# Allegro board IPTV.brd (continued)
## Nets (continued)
DDRA_ADDR13: R207.1 U9.T3(A13/NC)
DDRA_ADDR13_R: IC13.AL35(DDRA_ADR13) R207.2
DDRA_ADDR14: R200.1 U9.T7(NC5)
DDRA_ADDR14_R: IC13.AF38(DDRA_ADR14) R200.2
DDRA_BA0: R221.1 U9.M2(BA0)
DDRA_BA0_R: IC13.Y37(DDRA_BA0) R221.2
DDRA_BA1: R219.1 U9.N8(BA1)
DDRA_BA1_R: IC13.AA36(DDRA_BA1) R219.2
DDRA_BA2: R220.1 U9.M3(BA2)
DDRA_BA2_R: IC13.AA35(DDRA_BA2) R220.2
DDRA_CASN: R204.1 U9.K3(CAS)
DDRA_CASN_R: IC13.AL36(DDRA_CASN) R204.2
DDRA_CKE0: IC13.Y38(DDRA_CKE0) R188.2 U9.K9(CKE)
DDRA_CKN0: R259.1 R628.2 R629.1 R631.1 U9.K7(CK)
DDRA_CKN0_R: IC13.AH35(DDRA_CKN0) R259.2
DDRA_CKP0: R260.1 R626.1 R627.2 R631.2 U9.J7(CK*)
DDRA_CKP0_R: IC13.AH36(DDRA_CKP0) R260.2
DDRA_CSN0: R203.1 U9.L2(CS)
DDRA_CSN0_R: IC13.AM38(DDRA_CSN0) R203.2
DDRA_DM0: IC13.T37(DDRA_DM0) U9.E7(LDM)
DDRA_DM1: IC13.N38(DDRA_DM1) U9.D3(UDM)
DDRA_DQ0: IC13.H37(DDRA_DQ0) U9.F8(DQ3)
DDRA_DQ1: IC13.H38(DDRA_DQ1) U9.F7(DQ1)
DDRA_DQ2: IC13.G38(DDRA_DQ2) U9.H7(DQ7)
DDRA_DQ3: IC13.G37(DDRA_DQ3) U9.H8(DQ5)
DDRA_DQ4: IC13.T38(DDRA_DQ5) U9.E3(DQ0)
DDRA_DQ5: IC13.U38(DDRA_DQ4) U9.G2(DQ6)
DDRA_DQ6: IC13.U37(DDRA_DQ6) U9.H3(DQ4)
DDRA_DQ7: IC13.U36(DDRA_DQ7) U9.F2(DQ2)
DDRA_DQ8: IC13.L36(DDRA_DQ11) U9.D7(DQ8)
DDRA_DQ9: IC13.L37(DDRA_DQ9) U9.B8(DQ14)
DDRA_DQ10: IC13.L38(DDRA_DQ10) U9.A7(DQ12)
DDRA_DQ11: IC13.K38(DDRA_DQ8) U9.C8(DQ10)
DDRA_DQ12: IC13.P37(DDRA_DQ13) U9.A3(DQ15)
DDRA_DQ13: IC13.P38(DDRA_DQ12) U9.A2(DQ13)
DDRA_DQ14: IC13.R35(DDRA_DQ14) U9.C2(DQ11)
DDRA_DQ15: IC13.R36(DDRA_DQ15) U9.C3(DQ9)
DDRA_DQSN0: IC13.J36(DDRA_DQSN0) U9.G3(LDQS*)
DDRA_DQSN1: IC13.N35(DDRA_DQSN1) U9.B7(UDQS*)
DDRA_DQSP0: IC13.J35(DDRA_DQSP0) U9.F3(LDQS)
DDRA_DQSP1: IC13.N36(DDRA_DQSP1) U9.C7(UDQS)
DDRA_ODT0: R201.1 U9.K1(ODT)
DDRA_ODT0_R: IC13.AM36(DDRA_ODT0) R201.2
DDRA_RASN: R202.1 U9.J3(RAS)
DDRA_RASN_R: IC13.AM37(DDRA_RASN) R202.2
DDRA_REF\G: C288.2 C293.2 C294.1 IC13.N28(DDRA_REF1) IC13.R28(DDRA_REF2) IC13.Y28(DDRA_REF3) R191.2 R192.1
DDRA_RESETN\G: R189.2 R617.1 R619.1 R620.2 R638.1
DDRA_VREF_CA: C465.1 C466.1 C467.1 C468.2 R624.2 R625.1 U9.M8(VREFCA)
DDRA_VREF_DQ: C461.1 C462.1 C463.1 C464.2 R622.1 R623.2 U9.H1(VREFDQ)
DDRA_WEN: R231.1 U9.L3(WE)
DDRA_WEN_R: IC13.Y36(DDRA_WEN) R231.2
DDRB_ADDR0: R281.1 U10.N3(A0)
DDRB_ADDR0_R: IC13.C37(DDRB_ADR0) R281.2
DDRB_ADDR1: R261.1 U10.P7(A1)
DDRB_ADDR1_R: IC13.D29(DDRB_ADR1) R261.2
DDRB_ADDR2: R289.1 U10.P3(A2)
DDRB_ADDR2_R: IC13.B38(DDRB_ADR2) R289.2
DDRB_ADDR3: R287.1 U10.N2(A3)
DDRB_ADDR3_R: IC13.B32(DDRB_ADR3) R287.2
DDRB_ADDR4: R268.1 U10.P8(A4)
DDRB_ADDR4_R: IC13.C35(DDRB_ADR4) R268.2
DDRB_ADDR5: R272.1 U10.P2(A5)
DDRB_ADDR5_R: IC13.D33(DDRB_ADR5) R272.2
DDRB_ADDR6: R266.1 U10.R8(A6)
DDRB_ADDR6_R: IC13.B36(DDRB_ADR6) R266.2
DDRB_ADDR7: R284.1 U10.R2(A7)
DDRB_ADDR7_R: IC13.A32(DDRB_ADR7) R284.2
DDRB_ADDR8: R264.1 U10.T8(A8)
DDRB_ADDR8_R: IC13.C36(DDRB_ADR8) R264.2
DDRB_ADDR9: R280.1 U10.R3(A9)
DDRB_ADDR9_R: IC13.D32(DDRB_ADR9) R280.2
DDRB_ADDR10: R265.1 U10.L7(A10/AP)
DDRB_ADDR10_R: IC13.C29(DDRB_ADR10) R265.2
DDRB_ADDR11: R263.1 U10.R7(A11)
DDRB_ADDR11_R: IC13.A37(DDRB_ADR11) R263.2
DDRB_ADDR12: R277.1 U10.N7(A12/BC-)
DDRB_ADDR12_R: IC13.C32(DDRB_ADR12) R277.2
DDRB_ADDR13: R262.1 U10.T3(A13/NC)
DDRB_ADDR13_R: IC13.B37(DDRB_ADR13) R262.2
DDRB_ADDR14: R288.1 U10.T7(NC5)
DDRB_ADDR14_R: IC13.C33(DDRB_ADR14) R288.2
DDRB_BA0: R275.1 U10.M2(BA0)
DDRB_BA0_R: IC13.A28(DDRB_BA0) R275.2
DDRB_BA1: R267.1 U10.N8(BA1)
DDRB_BA1_R: IC13.A29(DDRB_BA1) R267.2
DDRB_BA2: R270.1 U10.M3(BA2)
DDRB_BA2_R: IC13.B29(DDRB_BA2) R270.2
DDRB_CASN: R278.1 U10.K3(CAS)
DDRB_CASN_R: IC13.D36(DDRB_CASN) R278.2
DDRB_CKE0: IC13.D27(DDRB_CKE0) R197.1 U10.K9(CKE)
DDRB_CKN0: R282.1 R643.2 R644.1 R645.1 U10.K7(CK)
DDRB_CKN0_R: IC13.B34(DDRB_CKN0) R282.2
DDRB_CKP0: R286.1 R641.1 R642.2 R645.2 U10.J7(CK*)
DDRB_CKP0_R: IC13.A34(DDRB_CKP0) R286.2
DDRB_CSN0: R269.1 U10.L2(CS)
DDRB_CSN0_R: IC13.D37(DDRB_CSN0) R269.2
DDRB_DM0: IC13.C25(DDRB_DM2) U10.E7(LDM)
DDRB_DM1: IC13.A22(DDRB_DM3) U10.D3(UDM)
DDRB_DQ0: IC13.B16(DDRB_DQ18) U10.H8(DQ5)
DDRB_DQ1: IC13.B17(DDRB_DQ17) U10.F8(DQ3)
DDRB_DQ2: IC13.A17(DDRB_DQ16) U10.F7(DQ1)
DDRB_DQ3: IC13.A16(DDRB_DQ19) U10.H7(DQ7)
DDRB_DQ4: IC13.B25(DDRB_DQ20) U10.F2(DQ2)
DDRB_DQ5: IC13.A25(DDRB_DQ21) U10.E3(DQ0)
DDRB_DQ6: IC13.A26(DDRB_DQ22) U10.G2(DQ6)
DDRB_DQ7: IC13.B26(DDRB_DQ23) U10.H3(DQ4)
DDRB_DQ8: IC13.A19(DDRB_DQ24) U10.B8(DQ14)
DDRB_DQ9: IC13.B19(DDRB_DQ25) U10.C8(DQ10)
DDRB_DQ10: IC13.B20(DDRB_DQ27) U10.A7(DQ12)
DDRB_DQ11: IC13.A20(DDRB_DQ26) U10.D7(DQ8)
DDRB_DQ12: IC13.B23(DDRB_DQ28) U10.A3(DQ15)
DDRB_DQ13: IC13.C23(DDRB_DQ30) U10.A2(DQ13)
DDRB_DQ14: IC13.A23(DDRB_DQ29) U10.C3(DQ9)
DDRB_DQ15: IC13.C24(DDRB_DQ31) U10.C2(DQ11)
DDRB_DQSN0: IC13.D18(DDRB_DQSN2) U10.G3(LDQS*)
DDRB_DQSN1: IC13.C21(DDRB_DQSN3) U10.B7(UDQS*)
DDRB_DQSP0: IC13.C18(DDRB_DQSP2) U10.F3(LDQS)
DDRB_DQSP1: IC13.D21(DDRB_DQSP3) U10.C7(UDQS)
DDRB_ODT0: R285.1 U10.K1(ODT)
DDRB_ODT0_R: IC13.D35(DDRB_ODT0) R285.2
DDRB_RASN: R274.1 U10.J3(RAS)
DDRB_RASN_R: IC13.D38(DDRB_RASN) R274.2
DDRB_REF\G: C309.2 C314.2 C315.1 IC13.L21(DDRB_REF1) IC13.L23(DDRB_REF2) IC13.L26(DDRB_REF13) R198.2 R199.1
DDRB_RESETN\G: R193.2 R636.1 R637.2
DDRB_VREF_CA: C469.1 C470.1 C471.1 C472.2 R639.2 R640.1 U10.M8(VREFCA)
DDRB_VREF_DQ: C474.1 C475.1 C478.1 C481.2 R634.2 R646.1 U10.H1(VREFDQ)
DDRB_WEN: R279.1 U10.L3(WE)
DDRB_WEN_R: IC13.B28(DDRB_WEN) R279.2
DIFF_HDMI_0N\G: IC13.AU22(HDMI_TX0M) U15.2 U15.9 XP1.9
DIFF_HDMI_0P\G: IC13.AV22(HDMI_TX0P) U15.1 U15.10 XP1.7
DIFF_HDMI_1N\G: IC13.AU23(HDMI_TX1M) U15.5 U15.6 XP1.6
DIFF_HDMI_1P\G: IC13.AV23(HDMI_TX1P) U15.4 U15.7 XP1.4
DIFF_HDMI_2N\G: IC13.AT24(HDMI_TX2M) U16.2 U16.9 XP1.3
DIFF_HDMI_2P\G: IC13.AR24(HDMI_TX2P) U16.1 U16.10 XP1.1
DIFF_HDMI_CLKN\G: IC13.AR21(HDMI_TXCN) U16.5 U16.6 XP1.12
DIFF_HDMI_CLKP\G: IC13.AT21(HDMI_TXCP) U16.4 U16.7 XP1.10
DIFF_USB0D_N\G: IC13.AU28(USB0_DM) R630.2
DIFF_USB0D_P\G: IC13.AV28(USB0_DP) R621.2
EBI_DQ0\G: IC2.29(I/O0) IC13.Y1(EBI_DQ0/GPIO4_0)
EBI_DQ1\G: IC2.30(I/O1) IC13.Y2(EBI_DQ1/GPIO4_1)
EBI_DQ2\G: IC2.31(I/O2) IC13.W1(EBI_DQ2/GPIO4_2)
EBI_DQ3\G: IC2.32(I/O3) IC13.W2(EBI_DQ3/GPIO4_3)
EBI_DQ4\G: IC2.41(I/O4) IC13.W3(EBI_DQ4/GPIO4_4)
EBI_DQ5\G: IC2.42(I/O5) IC13.W4(EBI_DQ5/GPIO4_5)
EBI_DQ6\G: IC2.43(I/O6) IC13.V3(EBI_DQ6/GPIO4_6)
EBI_DQ7\G: IC2.44(I/O7) IC13.V4(EBI_DQ7/GPIO4_7)
ENET_ACTIVITY_LEDB\G: IC13.AR1(TSI0_D2/VIU0_DAT2) R271.1
ENET_IND\G: IC13.AR2(TSI0_D3/VIU0_DAT3) R355.2
ETH_RSTN\G: R315.2 R364.2 R366.1
FE0_DUPLEX: IC8.16(RXD0/RXD0/DUPLE) R132.2 R311.2
FUNSEL\G: IC13.C13(FUNSEL) R230.1
HDMI_CEC\G: IC13.AV20(SIO2_DIN/GPIO2_6/HDMI_CEC) U14.1 XP1.13
HDMI_HOT_PLUG\G: C247.1 D20.3 IC13.AT19(SIO2_BCLK/GPIO2_3) R146.1 U14.6 XP1.19
I2C3_SCL\G: C178.1 IC13.AB2(NF_CSN1/I2C3_SCL) R38.1 R59.2
I2C3_SDA\G: C72.1 IC13.AC1(NF_RDY1/I2C3_SDA) R37.1 R62.2
IR_IN\G: D37.1(OUT) IC13.C11(GPIO5_4/IR_IN) R119.2
IR_LED_INDIC\G: IC13.AP2(TSI0_D1/VIU0_DAT1) LED12.2(C)
JTAG_SEL\G: IC13.AU7(JTAG_SEL/GPIO2_7) R45.1 R46.1 R81.1
LED0_LINK_ACT\G: R114.1 R130.2
LED_WLAN: LED8.2(C) R349.2
LNA_CORE_VDD1P2: C320.1 C322.1 FB1.1 U18.23(LNA_CORE1_VDD1P2) U18.27(LNA_CORE0_VDD1P2)
LOGEN_VDD1P2: C355.2 R333.1 U18.26(LOGEN_VDD1P2)
MDCK\G: IC8.12(MDC) R242.2
MDIO\G: IC8.11(MDIO) IC13.AU38(GPIO11_0/MDIO) R233.1
MUTE_CTL\G: IC13.C5(EBI_ADR3/GPIO7_1) R88.1(A)
NF_ADNUM\G: IC13.AT37(NF_ADNUM/GPIO0_0) R227.1 R236.1
NF_ALE\G: IC2.17(AL) R57.1
NF_BLKSIZE\G: IC13.AV37(NF_BLKSIZE/GPIO10_7) R224.1 R242.1
NF_BOOTBW\G: IC13.AA3(NF_WEN/NF_BOOTBW) R41.1 R42.1 R63.2
NF_CLE\G: IC2.16(CL) R58.1
NF_CSN0\G: IC2.9(E*) IC13.AB3(NF_CSN0/SDIO_CCMD) R98.1
NF_CSN1\G: R59.1 R143.2
NF_PAGE0\G: IC13.AR36(NF_PAGE0/GPIO0_1) R228.1 R235.1
NF_PAGE1\G: IC13.AR37(NF_PAGE1/GPIO0_2) R225.1 R234.1
NF_RDY0\G: IC2.7(RB*) IC13.AC2(NF_RDY0/SDIO_CARD_DETECT) R97.1
NF_RDY1\G: R62.1 R142.2
NF_REN\G: IC2.8(R*) IC13.AB1(NF_REN/SDIO_CARD_POWER_EN)
NF_WEN\G: IC2.18(W*) R63.1
NF_WP\G: IC2.19(WP*) R139.2
NFC_ECC0\G: IC13.B2(EBI_ADR15/GPIO11_6) R293.1 R297.1
NFC_ECC1\G: IC13.A2(EBI_ADR12/GPIO11_2) R223.1 R295.1
NFC_ECC2\G: IC13.D1(EBI_ADR11/GPIO11_1) R222.1 R229.1
PCIE_CLKOUTN: C194.2 R66.2 R73.1
PCIE_CLKOUTP: C193.2 R65.2 R72.1
PCIE_CLKREQ: R94.1 R319.2 R323.2 R354.2
PCIE_RDN: IC13.M4(PCIE_RX0M) R339.2
PCIE_RDP: IC13.M3(PCIE_RX0P) R337.2
PCIE_RST: R96.1 R106.2 R328.2 R341.2
PCIE_TDN: C358.1 R347.2
PCIE_TDP: C359.1 R343.2
PCIE_WAKE_L: R91.1 R93.2 R324.2 R325.2
PHY0_AD1: IC8.14(RXD2/PHYAD1) R312.2 R313.2
POWER_LED_INDIC\G: IC13.AP1(TSI0_D0/VIU0_DAT0) R457.1
RESET_DDR3\G: R620.1 R637.1 R647.2 R648.2
RESET_SYS\G: C338.1(A) IC13.C6(RESET_SYS) R20.2(B) R316.2 R647.1
RF_DISABLE_N: R99.1 R102.2 R327.2 R332.2
ROMBOOT_SEL\G: IC13.D9(ROMBOOT_SEL/SPI_SCLK) R47.1 R48.1
RX+_PHY0\G: R127.2 R309.1 TR2.6(RD+) U17.3
RX-_PHY0\G: R126.2 R303.1 TR2.8(RD_) U17.4
RXD0_RMII0: IC13.AP37(GPIO1_7/MII0_RXD0) R132.1
RXD1_RMII0: IC13.AP38(GPIO1_6/MII0_RXD1) R154.1
RXDV_RMII0: IC13.AR38(GPIO1_5/MII0_RXDV) R302.1
RXG_0: C238.1 U21.3(J2)
RXG_1: C334.1 U19.1(J3)
SD_CCLK_OUT: IC13.AU34(MII2_TXCK/PWM_OUT0) U12.5(P5)
SD_CCMD: R149.1 R239.2 U12.2(P2)
SD_CDATA0: R150.1 R160.2 U12.7(P7)
SD_CDATA1: R151.1 R296.2 U12.8(P8)
SD_CDATA2: R147.1 R238.2 U12.9(P9)
SD_CDATA3: R148.1 R237.2 U12.1(P1)
SD_CWPR: R152.1 R241.2 U12.11(P11)
SD_DETECT: R153.1 R292.2 U12.10(P10)
SD_POWER_EN: R164.2 R166.2 R294.2
SELF_BOOT\G: IC13.C9(SELF_BOOT/SPI_SDO) R43.1 R44.1
SFC_CLK\G: R64.2 TP1.1 U11.6(A1)
SFC_CSN1: IC13.AJ2(SFC_CS1N/GPIO12_6) R167.1 U11.1(SDA)
SFC_DIO: IC13.AK3(SFC_DIO/GPIO12_0) R157.2
SFC_DOI: IC13.AH2(SFC_DOI/GPIO12_3) R112.1
SFC_HOLDN: IC13.AJ1(SFC_HOLD_IO3/GPIO12_4) R170.1 U11.7(A0)
SFC_WPN: IC13.AJ3(SFC_WP_IO2/GPIO12_1) R168.1 R169.2 U11.3(ALERT)
SPDIF_OUT\G: R81.2 XS7.3
STBY_PWROFF\G: IC13.C12(GPIO5_2/GPIO9_4) R61.1 R68.2 R69.2 R82.1 R89.1 R251.1
SYNTH_VCO_VDD1P2: C325.2 FB3.2 U18.36(SYNTH_VCO_VDD1P2)
SYNTH_VDD1P2: C329.2 FB2.2 U18.37(SYNTH_VDD1P2)
TCK_ICE\G: IC13.B14(JTAG_TCK) R249.1
TDI: R344.2 R349.1 U18.3(GPIO3/LED_WLAN/TDI)
TDI_ICE\G: IC13.A13(JTAG_TDI) R245.1
TDO_ICE\G: IC13.C14(JTAG_TDO) R244.1
TMS_ICE\G: IC13.A14(JTAG_TMS) R248.1
TRST_ICE\G: IC13.B13(JTAG_TRSTN) R250.1
TX+_PHY0\G: R129.2 R310.2 TR2.1(TD+) U17.1
TX-_PHY0\G: R128.2 R308.2 TR2.3(TD_) U17.6
TX_2G_CORE_VDD1P2: C241.1 C249.2 C374.1 R318.2 U18.21(TX_2G_CORE1_VDD1P2) U18.29(TX_2G_CORE0_VDD1P2)
TXD0_RMII0\G: IC8.24(TXD0/TXD0) R235.2
TXD1_RMII0\G: IC8.25(TXD1/TXD1) R236.2
TXEN_RMII0: IC8.23(TXEN/TX_EN) R234.2
TXG_0: C228.1 L31.2 R334.2
TXG_0_SW_IN: C332.1 R336.2 U21.1(J3)
TXG_1: C327.1 L26.2 R252.2
TXG_1_SW_IN: C373.1 R345.2 U19.3(J2)
UART0_RXD\G: IC13.AU25(GPIO3_0/UART0_RXD) R485.1
UART0_TXD\G: IC13.AV25(GPIO3_1/UART0_TXD) R479.1
USB0_PWREN\G: IC13.AU26(USB0_PWREN/GPIO7_7) R103.2 R253.1 R301.1
USB1_PWREN\G: IC13.AT25(I2C1_SDA/USB1_PWREN) R107.2 R322.1 R329.1
USB1D_DM\G: IC13.AV29(USB1_DM) R604.2 U1.21(DMU)
USB1D_DP\G: IC13.AU29(USB1_DP) R603.2 U1.22(DPU)
USB_HUB_RST\G: C418.1 R363.2 R589.2 U1.37(SYSRSTB)
USB_HUB_XI: C422.1 R591.1 U1.10(X1) U2.1
USB_HUB_XO: C423.1 R590.2 R591.2 U2.3
USBHUB1_DM: R592.2 U3.3 XS5.2(D-)
USBHUB1_DP: R593.2 U3.4 XS5.3(D+)
USBHUB1_FLG: R606.2 U1.46(CSB1) U5.2(FLG)
USBHUB1_PWREN: R605.2 U1.45(PPB1) U5.1(EN)
USBHUB1_VBUS: C424.1 C425.1 R632.1 U5.6(OUT1) U5.8(OUT2) XS5.1(V)
USBHUB2_DM: R594.2 R604.1 U4.6 XS1.2(D-)
USBHUB2_DP: R595.2 R603.1 U4.1 XS1.3(D+)
USBHUB2_FLG: R609.2 U1.44(CSB2) U6.2(FLG)
USBHUB2_PWREN: R608.2 U1.43(PPB2) U6.1(EN)
USBHUB2_VBUS: C428.1 C431.1 L57.2 R633.1 U6.6(OUT1) U6.8(OUT2)
USBHUB3_DM: R596.2 R630.1 U4.3 XS10.2(D-)
USBHUB3_DP: R597.2 R621.1 U4.4 XS10.3(D+)
USBHUB3_FLG: R612.2 U1.41(CSB3) U7.2(FLG)
USBHUB3_PWREN: R611.2 U1.40(PPB3) U7.1(EN)
USBHUB3_VBUS: C432.1 C435.1 L51.2 R649.1 U7.6(OUT1) U7.8(OUT2)
USBHUB4_DM: R598.2 U3.1 XS4.2(D-)
USBHUB4_DP: R599.2 U3.6 XS4.3(D+)
USBHUB4_FLG: R615.2 U1.39(CSB4) U8.2(FLG)
USBHUB4_PWREN: R614.2 U1.38(PPB4) U8.1(EN)
USBHUB4_VBUS: C436.1 C439.1 R650.1 U8.6(OUT1) U8.8(OUT2) XS4.1(V)
VREG3P3: C365.1 R321.2 U18.35(VREG3P3_VDD3P3)
XIN\G: C272.1 IC13.A7(XIN) R186.1 XL1.1
XOUT\G: IC13.B7(XOUT) R186.2 R187.2
XTAL_IN: C242.1 U18.39(XTAL_IN) Y4.3
XTAL_OUT: R351.1 U18.38(XTAL_OUT)
XTAL_VDD2P5: C367.1 U18.40(XTAL_VDD2P5)
N305458: C25.2 C41.2 IC13.L17(DVDD33_STANDBY) L7.1
N331283: C20.2 C40.2 IC13.K17(VDD_STANDBY) L1.1
N371060: IC13.AN34(VPP_OTP) R36.1
N550713: C7.1 C19.1 C21.1 C157.1 C173.1 IC13.K14(VDDHV25_PLL_5) IC13.K15(VDDHV25_PLL_1) IC13.K16(VDDHV25_PLL_2) L2.1
N600656: C24.1 C158.1 C159.1 C162.1 C175.1 IC13.P15(VDDLV10_PLL5) IC13.P16(VDDLV10_PLL_1) IC13.P17(VDDLV10_PLL_2) L3.1
N617373: IC13.L1(PCIE_REFCLKP) R65.1
N617477: IC13.L2(PCIE_REFCLKM) R66.1
N620918: IC13.N10(PCIE_REXT) R71.1
N621324: C63.1 C67.2 C196.2 IC13.P11(PCIE_VP10_1) IC13.R11(PCIE_VP10_2) IC13.T11(PCIE_VP10_3) L5.1
N624580: C48.1 C180.2 C186.2 IC13.P10(PCIE_VP25_1) IC13.R10(PCIE_VP25_2) L6.1
N629124: IC13.AG4(SATA_REFCLKP) R70.1
N629220: IC13.AG3(SATA_REFCLKM) R70.2
N630094: IC13.W10(SATA_REXT) R67.1
N631154: C199.1 C200.2 C201.2 IC13.AA11(SATA_VP10_1) IC13.Y11(SATA_VP10_2) L8.1
N635359: C197.1 C198.2 IC13.AA10(SATA_VP25_1) IC13.Y10(SATA_VP25_2) L16.1
N672491: IC13.C2(EBI_ADR8/GPIO2_7) R54.1 R56.2
N675190: IC13.D2(EBI_ADR9/GPIO3_0) R52.1 R53.2
N675584: IC13.D3(EBI_ADR10/GPIO3_1) R49.1 R50.2
N683964: IC13.AJ4(SFC_CLK/GPIO12_2) R64.1
N742106: IC13.D25(DDRB_RESETN) R193.1
N743329: IC13.C16(DDRB_RTT) R194.1
N743719: IC13.K29(DDRB_HI) R195.1
N744113: IC13.L28(DDRB_LO) R196.1
N849049: IC13.V36(DDRA_RESETN) R189.1
N854645: IC13.G36(DDRA_RTT) R190.1
N855285: IC13.AB29(DDRA_HI) R17.1
N858511: IC13.AB28(DDRA_LO) R283.1
N952727: C26.2 C56.2 IC13.AB10(AVDD25_QAM) L34.2
N952924: C28.2 C57.2 IC13.AC11(AVDD10_QAM) L35.2
N965277: IC13.AT27(USB_REXT) R226.2
N968462: C30.1 C58.1 C59.1 IC13.AR27(AVDD33_USB1) IC13.AT28(AVDD33_USB2) L36.2
N1067717: C31.2 C61.2 IC13.AH25(DVDD10_USB) L37.1
N1077748: IC13.AP36(GPIO5_4/ETH0_REFCLK) R232.1
N1078134: C243.2 R232.2 R240.1
N1094266: IC13.AT36(ETH2_REFCLK/ETH1_REFCLK) R241.1
N1103649: IC13.AT33(USB0_OVRVUR/NFC_ECC_TYPE1) R237.1
N1103990: IC13.AU32(USB0_PWREN/NFC_ECC_TYPE0) R238.1
N1109849: IC13.AT34(USB1_PWREN/NFC_ECC_TYPE2) R239.1
N1115694: IC13.AT30(MII2_CRS/USB0_PWREN) R294.1
N1152398: JP1.3 R111.1 R485.2
N1152811: JP1.2 R101.1 R479.2
N1383679: IC13.AT12(VDAC0_IREF) R75.2 R77.2
N1387604: C202.2 C207.2 IC13.AT11(VDAC0_VDREF)
N1390073: C214.1 C217.1 C220.1 C221.1 IC13.AH14(AVDD3V3_VDAC0_1) IC13.AJ13(AVDD3V3_VDAC0_2) IC13.AJ14(AVDD3V3_VDAC0_3) IC13.AR10(AVDD3V3_VDAC0_4) L21.2
N1408395: IC13.AT13(VDAC1_IREF) R74.2 R76.2
N1409767: C205.2 C212.2 IC13.AR14(VDAC1_VDREF)
N1414099: C213.1 C215.1 C216.1 C219.1 IC13.AH15(AVDD3V3_VDAC1_1) IC13.AH16(AVDD3V3_VDAC1_2) IC13.AJ15(AVDD3V3_VDAC1_3) L22.2
N1446091: IC13.AU20(HDMI_REXT) R79.1 R80.1
N1450972: C227.1 C231.1 C233.1 C235.1 C236.1 C237.1 IC13.AH20(AVCC10_HDMI_1) IC13.AJ20(AVCC10_HDMI_2) IC13.AR22(AVCC10_HDMI_3) IC13.AT22(AVCC10_HDMI_4) L24.1
N1496909: C232.1 C234.1 IC13.AT8(ADAC_VCM)
N1501073: C223.1 C225.1 IC13.AT9(ADAC_VREFDAC)
N1511391: C226.1 C229.1 C230.1 IC13.AH10(AVDD33_ADAC_1) IC13.AJ10(AVDD33_ADAC_2) IC13.AR8(AVDD33_ADAC_3) L23.1
N1721272: C222.2 Q5.1(GATE) Q6.1(GATE) Q7.1(GATE) R9.2 R78.1 R84.1 R86.1
N1729801: R9.1 T7.3(C)
N1743891: R69.1 T7.1(B)
N1825143: C307.1(A) C308.2 D37.3(VS) R509.2
N1834854: LED10.1(COM) R414.2
N1835472: R355.1 R365.1 R368.1 R414.1
N1837681: LED10.2(R) R365.2 R410.1 T3.3(C)
N1839934: R410.2 T6.1(B)
N1841130: LED10.3(GY) T6.3(C)
N1846118: R273.2 R276.1 T3.1(B)
N1848580: R271.2 R273.1
N1851731: LED11.2(R) R472.2 R473.1 T4.3(C)
N1851759: R473.2 T5.1(B)
N1851767: LED11.3(GY) T5.3(C)
N1851843: R457.2 R458.1 T4.1(B)
N1851925: LED11.1(COM) R474.2
N2007180: C36.1 R28.2 R163.1
N2007522: IC9.6(OUT3) R28.1
N2007610: IC9.7(OUT2) TP31.1
N2007630: IC9.8(OUT1) TP30.1
N2053816: C92.1 C169.2 C171.2 IC5.1(VO) L12.1 L15.2 R87.2
N2054287: C92.2 IC5.2(VFB) R85.2 R87.1
N2062131: IC5.7(EN) R100.2
N2068150: C163.2 IC5.4(SS)
N2072854: C165.2 IC5.10(SW1) IC5.11(SW2) L15.1
N2075428: C165.1 IC5.12(VBST)
N2101818: C167.1 IC5.3(VREG5)
N2116419: C85.1 Q8.1(GATE) R254.2 R255.1 R301.2
N2117665: R254.1 T2.3(C)
N2151179: R103.1 T2.1(B)
N2292443: IC2.10(NC6) R143.1
N2293018: IC2.6(NC5) R142.1
N2300583: IC2.38(NC23) R144.1 R145.2
N2472672: C86.1 IC12.8(SS)
N2473836: C89.1 C174.1 IC12.6(COMP)
N2474741: C89.2 R104.1
N2480908: IC12.7(EN) R82.2 R123.1
N2490139: C93.2 IC12.1(BS)
N2491369: C93.1 IC12.3(SW) L10.1
N2496811: IC12.5(FB) R108.2 R109.1
N2616362: C47.1 C87.1 C107.2 C109.2 IC26.1(VO) L11.2 L14.1 R60.2
N2616386: C97.2 IC26.10(SW1) IC26.11(SW2) L11.1
N2616524: IC26.7(EN) R61.2 R134.1 R135.1
N2616548: C97.1 IC26.12(VBST)
N2616572: C108.1 IC26.3(VREG5)
N2616768: IC26.2(VFB) R15.2 R55.2 R60.1
N2616804: C94.2 IC26.4(SS)
N2642107: C115.1 IC14.8(SS)
N2642151: C116.1 C117.1 IC14.6(COMP)
N2642251: C116.2 R116.1
N2642341: C120.2 IC14.1(BS)
N2642373: C120.1 IC14.3(SW) L20.1
N2642473: IC14.7(EN) R124.1
N2642609: IC14.5(FB) R120.2 R121.1
N2653412: C348.1 IC17.8(SS)
N2653456: C118.1 C349.1 IC17.6(COMP)
N2653460: C346.1 C347.2 R51.1 R125.2
N2653540: C349.2 R583.1
N2653646: C350.2 IC17.1(BS)
N2653678: C350.1 IC17.3(SW) L46.1
N2653726: C37.1 C351.1 C352.1 C354.1 C380.1 L38.1 L46.2 R563.1
N2653778: IC17.7(EN) R89.2 R125.1
N2653914: IC17.5(FB) R563.2 R567.1
N2753223: XP2.1 XS2.1
N2764036: C110.1 C119.2 L18.1 R16.1 R18.1
N2782469: R16.2 R18.2 XP2.2
N2794854: LED1.2(C) R122.1
N2978313: L56.1 L57.1 XS1.1(V)
N2982528: L51.1 L55.1 XS10.1(V)
N2987765: C274.1 R187.1 XL1.2
N4126175: R584.1 R585.2 U1.47(VBUSM)
N4126191: C413.1 C414.1 L49.2 R587.1 U1.16(AVSS_R) U1.18(AVSS)
N4126235: R595.1 U1.29(DP2)
N4126359: R594.1 U1.28(DM2)
N4126443: R586.2 U1.13(BUS_B)
N4126465: R593.1 U1.26(DP1)
N4126501: R592.1 U1.25(DM1)
N4126581: C404.1 C405.1 L47.2 R585.1
N4126617: R590.1 U1.11(X2)
N4126645: R587.2 U1.15(RREF)
N4126967: C413.2 C414.2 L48.2 U1.17(AVDD1) U1.19(AVDD2)
N4126991: R588.2 U1.14(TEST)
N4127321: R598.1 U1.34(DM4)
N4127377: R599.1 U1.35(DP4)
N4127493: R597.1 U1.32(DP3)
N4127601: R596.1 U1.31(DM3)
N4207901: R600.1 U1.8(AMBER)
N4556901: R607.1 U5.5(ILIM)
N4601170: R610.1 U6.5(ILIM)
N4602996: R613.1 U7.5(ILIM)
N4604860: R616.1 U8.5(ILIM)
N4652480: C0603.1 R617.2 U9.T2(RST)
N4662264: R618.2 U9.L8(ZQ)
N4946648: R635.2 U10.L8(ZQ)
N4946958: C473.1 R638.2 U10.T2(RST)
N5731377: R157.1 U11.5(A2)
N5731391: R112.2 U11.2(SCL)
N5767868: IC13.AT32(USB1_PWREN/SDIO_CDATA0) R160.1
N5876384: IC13.AR30(MII2_COL/USB0_OVRCUR) R292.1
N5917875: IC13.AV32(USB1_OVRCUE/SDIO_CDATA1) R296.1
N6200242: C239.1 IC8.32(RST*) R298.1 R315.1 R316.1 R367.1
N6200318: C113.2 IC8.10(REXT) R113.1
N6200334: LED5.2(C) R114.2
N6200500: IC8.28(COL/CONFIG0) R118.1
N6200912: IC8.26(TXD2) R299.2
N6200944: IC8.27(TXD3) R300.2
N6201102: IC8.18(RXDV/CRSDV/CONFIG) R302.2
N6210871: R307.1 XS11.A7(P7) XS11.A8(P8)
N6210911: C152.2 R303.2 R309.2
N6210999: TR2.16(TX+) XS11.A1(TX+)
N6211019: TR2.14(TX_) XS11.A2(TX-)
N6211031: R306.1 XS11.A4(P4) XS11.A5(P5)
N6211051: TR2.11(RX+) XS11.A3(RX+)
N6211151: R305.1 TR2.15(CT3)
N6211171: R304.1 TR2.10(CT2)
N6211183: TR2.9(RX_) XS11.A6(RX-)
N6211413: C151.2 R308.1 R310.1
N6211447: C161.2 R304.2 R305.2 R306.2 R307.2
N6323561: IC8.15(RXD1/RXD1/PHYAD) R154.2
N6351542: IC8.13(RXD3/PHYAD) R314.2
N6375056: IC8.4(RX-) R126.1
N6376252: IC8.5(RX+) R127.1
N6391887: IC8.6(TX-) R128.1
N6393086: IC8.7(TX+) R129.1
N6403944: IC8.30(LED0/NWAYEN) R130.1
N6828557: IC8.31(LED1/SPEED) R131.1
N6828959: R131.2 TP33.1
N7088770: C27.1 C29.1 CAP3.1(A) L29.1 R19.2 TP10.1 U13.2(OUT) U13.4(H/S OUT)
N7088794: C46.2 R12.2 R19.1 U13.1(ADJ)
N16840469: IC13.R3(EBI_DQ13/GPIO6_5) R323.1
N16871257: IC13.T4(EBI_DQ12/GPIO6_4) R325.1
N16883109: IC13.B4(EBI_ADR14/GPIO11_5) R327.1
N16907829: IC13.T3(EBI_DQ11/GPIO6_3) R328.1
N16928233: C358.2 IC13.N1(PCIE_TX0P)
N16929752: C359.2 IC13.N2(PCIE_TXOP)
N17005896: R107.1 T8.1(B)
N17005931: C88.1 Q10.1(GATE) R322.2 R330.2 R331.1
N17006006: R330.1 T8.3(C)
N17042686: C250.1 U18.44(O_VREF_LDO)
N17042698: R353.2 U18.46(O_VDD1P3_RF)
N17042736: ANT1.1 C323.1 C372.1
N17042751: C373.2 L44.2 R252.1
N17042774: C240.1 C332.2 L39.2 L42.2 R334.1
N17042778: C240.2 L40.2
N17042826: R335.2 U18.1(GPIO5/BT_RST_N/EXT_POR_L)
N17042890: ANT2.1 C324.1 C376.1
N17042953: C224.1 R351.2 Y4.1
N17043028: R340.1 U18.34(RCAL_RES_EXT)
N17043046: C327.2 U18.18(PA_2G_CORE1)
N17043052: C334.2 U18.22(RF_2G_ANTENNA_CORE1)
N17043079: C356.2 R337.1
N17043089: C357.2 R339.1
N17043097: C357.1 U18.62(TDN0)
N17043198: R319.1 U18.55(PCIE_CLKREQ_L)
N17043200: L43.1 U23.4(SW)
N17043207: R338.1 R342.2 U18.47(JTAG_SEL)
N17043263: C335.2 R348.2 R350.2 U23.6(FB)
N17043371: C228.2 U18.32(PA_2G_CORE0)
N17043377: C238.2 U18.28(RF_2G_ANTENNA_CORE0)
N17043650: LED8.1(A) R29.1
N17043923: C194.1 U18.60(REFCLK_N)
N17044492: R343.1 U18.65(RDP0)
N17044502: R347.1 U18.66(RDN0)
N17044512: C356.1 U18.63(TDP0)
N17044516: C193.1 U18.59(REFCLK_P)
N17044572: R341.1 U18.58(PERST_L)
N17044582: R332.1 U18.57(RF_DISABLE_L)
N17044593: R324.1 U18.48(PCIE_PME_I)
N17408441: ANT3.1 C385.1 C387.1
N17408443: ANT6.1 C386.1 C387.2
N17411597: ANT4.1 C388.1 C390.1
N17411599: ANT5.1 C389.1 C390.2
N17473278: IC9.1(IN1) R115.2
N17474165: IC9.2(IN2) R117.2
N17571775: D5.2(K) L2.2 R178.2
N17602669: R20.1(A) R256.2(B) U20.2(VCC)
N17602677: C391.1(A) R356.2(B) R357.2(B) R397.2(B) U20.3(R\E\S\E\T\)
N17621483: C60.2(B) R136.1(A) U22.13(-INL)
N17621510: R7.2(B) R247.1(A) R258.2(B)
N17621572: C181.1 R137.2(B) R317.1(A) R359.1(A)
N17621582: C34.2(B) U22.8(CP)
N17621588: R7.1(A) U22.11(UVP)
N17621590: C35.2 U22.6(PVSS)
N17621599: C62.2(B) R257.2(B) R359.2(B) R360.1 U22.3(OUTR)
N17621615: C62.1(A) R317.2(B) U22.2(-INR)
N17621623: C268.2(B) R137.1(A)
N17621625: C34.1(A) U22.7(CN)
N17621631: C60.1(A) R133.1 R358.1(A) R361.1(A) U22.12(OUTL)
N17621647: C182.1 R90.1(A) R136.2(B) R358.2(B)
N17621657: C393.1(A) R90.2(B)
N17621659: C53.1(A) R88.2(B) R246.1(A) U22.5(EN)
N17668644: C255.2 Q9.1(GATE) R10.2 R165.1
N17668703: R10.1 T9.3(C)
N17668713: R164.1 T9.1(B)
N17692840: IC13.AU36(PWM_OUT1/I2C0_SDA) R363.1
N17694055: IC13.AU35(PWM_OUT2/I2C0_SCL) R364.1
N17732186: IC13.AU10(VDAC0_IOUT2) R171.2
N17732471: IC13.AV10(VDAC0_IOUT1) R172.2
N17732758: IC13.AV11(VDAC0_IOUT0) R173.2
N17739492: IC13.AV14(VDAC1_IOUT0) R177.1
N17739788: IC13.AU14(VDAC1_IOUT1) R176.1
N17782138: D6.1(A) L29.2
N17812204: LED12.1(A) R475.2
N17850380: R397.1(A) TP19.1

Pads without a net: IC2 1 2 3 4 5 11 14 15 20 21 22 23 24 25 26 27 28 33 34 35 39 40 45 46 47 48; IC5 6; IC8 8 19 20 21 22 29; IC13 A4 A5 A10 A11 AC37 AC38 AE1 AE3 AE4 AF1 AH1 AL1 AL2 AM1 AM2 AN3 AN4 AP3 AR3 AR4 AR5 AR6 AR15 AR16 AR18 AT2 AT3 AT4 AT5 AT6 AT15 AT16 AT18 AT26 AT35 AU1 AU2 AU3 AU4 AU5 AU16 AU17 AV2 AV4 AV5 AV16 AV17 AV26 AV34 AV35 B1 B3 B5 B10 B11 C3 C4 C8 C26 C27 C31 D4 D5 D8 D26 D31 E1 E2 E3 E4 G1 G2 G3 H1 H2 H3 J3 J4 K3 K4 R4 T1 T2 U1 U2 W36 W37 W38; IC26 6; JP1 5; MARK1 1; MARK2 1; MARK3 1; MARK4 1; MARK5 1; MARK6 1; TR2 4 5 12 13; U1 3 4 5 6 7; U5 4; U6 4; U7 4; U8 4; U9 J1 J9 L1 L9 M7; U10 J1 J9 L1 L9 M7; U18 2 4 5 8 9 10 11 24 25 33 41 50 52 54; U23 1; XP1 14

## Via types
v1: diameter 0.508, hole 0.305, TOP to BOTTOM, 1769 vias
v2: diameter 0.457, hole 0.254, TOP to BOTTOM, 615 vias
v3: diameter 1.27, hole 0.762, TOP to BOTTOM, 25 vias
v4: diameter 2.032, hole 1.524, TOP to BOTTOM, 3 vias

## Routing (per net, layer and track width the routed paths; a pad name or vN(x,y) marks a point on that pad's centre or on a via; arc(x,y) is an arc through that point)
1V0\G: length 124.9
  TOP w0.508: v1(71.1,5.12) 40.98,5.12 38.91,7.19 38.91,26.88 30.84,34.96 30.84,39.91 32.51,41.59 32.51,50.62 33.49,51.6 33.5,51.6 37.95,56.04 v1(37.95,62.32)
  BOTTOM w0.508: v1(37.95,62.32) 40.79,62.32 v1(44.3,65.82) ; v1(71.1,5.12) 75.82,9.84 75.82,15.17 78.08,17.44 78.08,19.34 77.19,20.23 L1.2 L3.2
1V0_CTRL\G: length 37.9
  TOP w0.305: v2(73.15,35.96) 73.55,36.36 IC13.P19 ; v2(72.35,35.96) 72.75,36.36 IC13.P20
  TOP w0.381: v2(77.95,43.97) 77.56,43.57 IC13.AC14 ; IC13.AE16 75.95,45.17 v2(76.35,45.57) ; IC13.AC25 68.75,43.57 v2(69.15,43.97) IC13.AD25 ; IC13.W25 v2(69.15,39.97) ; IC13.P22 71.15,36.36 v2(70.75,35.96) ; IC13.AE23 70.35,45.17 v2(70.75,45.57) ; IC13.AE24 69.55,45.17 v2(69.95,45.57) ; IC13.AE22 71.15,45.17 v2(71.55,45.57) ; IC13.AB25 v2(69.15,42.37) ; IC13.AA14 77.56,41.97 v2(77.95,42.37) ; IC13.Y25 68.75,41.17 v2(69.15,40.77) ; IC13.AE20 72.75,45.17 v2(73.15,45.57) ; IC13.R25 68.76,37.17 v2(69.15,37.56) IC13.T25 ; v2(77.95,39.17) 77.55,39.57 IC13.V14 ; IC13.P24 69.55,36.36 v2(69.15,35.96) ; IC13.AE15 76.75,45.17 v2(77.15,45.57) ; v2(73.95,45.57) 73.55,45.17 IC13.AE19 ; v2(77.95,38.36) 77.55,38.77 IC13.U14 ; IC13.P23 70.35,36.36 v2(69.95,35.96) ; IC13.AE17 75.15,45.17 v2(75.55,45.57) ; IC13.U25 68.75,38.77 v2(69.15,38.36) ; v2(77.95,44.77) 77.56,44.37 IC13.AD14
  BOTTOM w0.381: v2(77.95,38.36) 77.59,38 L8.2 ; v2(70.75,35.96) 71.47,36.68 C11.1 ; v2(75.55,40.77) 74.76,40.77 C23.1 74.76,39.97 v2(75.55,39.97) ; C10.1 70.04,45.48 v2(69.95,45.57) 69.95,45.87 69.42,46.4 L24.2 ; C14.1 v2(73.15,35.96) ; C6.1 69.87,39.08 v2(69.15,38.36) ; C2.1 v2(77.95,39.17) ; C42.1 69.07,40.85 v2(69.15,40.77) ; C42.1 68.38,41.57 67.96,41.98 L37.2 ; C42.1 69.07,42.28 v2(69.15,42.37) ; C16.1 v2(73.15,45.57) ; v2(77.95,44.77) 77.87,44.85 C17.1 v2(77.15,45.57) 77.15,45.98 77.53,46.37 78.35,46.37 78.77,45.95 L35.1 ; C3.1 v2(69.95,35.96) ; v2(77.95,42.37) 77.24,41.65 C13.1 ; C8.1 v2(75.55,45.57) ; L5.2 77.95,35.96 v2(77.15,36.76) ; C9.1 v2(71.55,45.57) ; C177.1 69.07,43.88 v2(69.15,43.97)
  vias: v1(47.85,71.67) v1(47.85,71.03) v1(48.62,71.67) v1(48.62,71.03) v1(49.38,71.67) v1(49.38,71.03)
1V5_DDR3\G: length 74
  TOP w0.356: U10.G7 49.71,10.21 49.31,10.61 v2(49.31,10.61) ; v2(34.01,44.74) 34.26,44.74 U9.N9 ; v2(52.52,13.81) 52.12,14.21 U10.D2 ; U10.A1 54.52,15.01 v2(54.92,15.41) ; U9.C1 41.88,37 v2(42.14,36.74) ; v2(44.93,15.88) 44.91,15.86 U10.N1 ; U10.R1 43.31,15.61 v2(43.31,15.62) ; U9.R1 v2(41.48,46.6) ; U10.H9 48.91,8.12 v2(49.12,7.91) ; U9.D9 v2(34.12,37.4) ; U9.C9 34.52,37 v2(34.12,36.6) ; U10.C1 v2(52.52,14.61) ; v2(33.91,38.61) 33.92,38.6 34.52,38.6 U9.E9 ; v2(34.12,47) 34.52,46.6 U9.R9 ; U10.C9 52.92,8.61 v2(53.32,8.21) ; v2(54.12,14.61) 53.72,14.21 U10.B2 ; U10.K8 v2(47.71,9.01) ; U10.D9 v2(52.52,8.21) ; v2(50.49,15.62) 50.49,15.03 U10.F1 ; U9.G7 v2(35.72,39.8) ; v2(33.91,41.02) 33.93,41 U9.H9 ; U10.A8 54.52,9.41 54.53,9.4 v2(55.12,9.4) ; U9.D2 40.12,37.8 v2(40.52,37.4) ; U9.B2 40.12,36.2 v2(40.52,35.8) ; v2(51.72,8.21) 51.69,8.24 51.69,8.24 U10.E9 ; U9.F1 v2(41.53,39.4) ; U9.N1 v2(41.48,45)
  TOP w0.406: U10.K2 v2(47.71,13.81) ; U10.H2 v2(49.31,13.81) ; U9.K8 v2(34.92,42.2) ; v2(39.72,43) 39.73,43 39.73,42.99 39.73,42.99 40.12,42.6 U9.K2 ; R626.2 41.81,51.69 42.25,52.13 v1(42.27,52.13) ; v1(43.38,21.75) 43.17,21.97 R641.2 ; v2(41.27,34.92) 40.92,35.28 U9.A1 ; R644.2 v1(39.65,22.76) ; U9.H2 39.72,41.4 v2(39.72,41.4) ; U9.A8 v2(34.92,35.8) ; U10.R9 43.31,8.61 v2(42.91,8.21) ; R629.2 v1(42.04,54.76) ; U10.N9 v2(45.31,8.21)
  BOTTOM w0.356: C464.1 36.6,37.21 v2(36.6,37.34) ; v2(34.12,36.6) 33.84,36.32 C451.1 ; v2(35.72,39.8) 35.62,39.9 C446.1 ; C453.1 33.31,37.4 v2(34.12,37.4)
  BOTTOM w0.406: C459.1 39.97,42.75 39.73,42.99 39.73,42.99 39.73,43 v2(39.72,43) ; C491.1 45.19,8.08 v2(45.31,8.21) ; v2(55.12,9.4) 55.75,8.76 C484.1 ; C492.1 43.03,8.1 v2(42.91,8.21) ; C496.1 55.52,6.49 v1(55.47,6.53) ; C454.1 41.3,46.42 v2(41.48,46.6) ; C480.1 52.46,13.75 v2(52.52,13.81) ; C460.1 v1(33.76,49.44) ; C441.1 33.63,40.74 v2(33.91,41.02) ; C449.1 41.46,39.47 v2(41.53,39.4) ; C450.1 31.34,49.44 v1(30.84,48.93) ; v2(39.72,41.4) 39.63,41.31 39,41.31 C457.1 ; v2(48.13,15.91) 48.13,16.19 49.23,17.28 C481.1 ; 52.46,6.54 R640.2 52.62,8.11 v2(52.52,8.21) 52.52,8.26 53.16,8.9 C495.1 ; v2(50.49,15.62) 50.18,15.31 C488.1 ; C455.1 41.21,45.27 v2(41.48,45) ; R619.2 v1(36.84,18.83) ; v2(34.01,44.74) 33.64,45.11 C443.1 ; C472.1 49.12,7.7 v2(49.12,7.91) 48.79,8.24 C485.1 ; C468.1 v1(31.5,48.39) ; v2(47.71,13.81) 47.24,13.34 C482.1 ; C448.1 40.62,35.7 v2(40.52,35.8) ; C490.1 49.26,13.87 v2(49.31,13.81) ; C452.1 34.77,35.65 v2(34.92,35.8) ; v2(52.52,14.61) 53,14.12 C487.1 ; C444.1 33.88,47.14 34,47.12 v2(34.12,47) ; R622.2 v1(36.83,32.6) ; v2(53.32,8.21) 53.91,7.61 C486.1 ; C476.1 43.31,14.91 v2(43.31,15.62) ; v2(47.71,9.01) 47.24,8.54 C483.1 ; C494.1 51.53,8.21 v2(51.72,8.21) ; v2(54.92,15.41) 55.43,15.41 C477.1 ; C447.1 40.54,37.38 v2(40.52,37.4) ; C489.1 49.11,10.4 v2(49.31,10.61) ; C458.1 v2(41.27,34.92) ; v2(54.12,14.61) 54.61,14.61 54.71,14.71 C479.1 ; v2(34.92,42.2) 34.96,42.16 C442.1 ; R646.2 v1(56.85,17.59) ; C493.1 v1(40.13,14.1) ; R636.2 38.2,24.82 v1(38.2,24.29) ; R625.2 v1(31.88,44.58) ; C497.1 v1(40.77,9.05) ; v2(42.14,36.74) C456.1 ; v2(33.91,38.61) C445.1
  vias: v1(35.03,26.2) v1(35.03,25.31) v1(35.66,26.2) v1(35.66,25.31)
1V5_DDR3_PHY\G: length 84.4
  TOP w0.305: v2(61.15,30.36) 61.52,30.73 ; v2(70.36,28.93) 70.36,28.83 70.35,28.82 IC13.D23 ; IC13.AN36 59.95,51.57 v2(60.35,51.17)
  TOP w0.356: IC13.V35 60.75,39.57 v2(61.15,39.97) ; IC13.AG36 v2(60.35,46.37) ; IC13.Y35 60.75,41.17 v2(61.15,41.57) ; v2(59.55,29.56) 59.15,29.17 IC13.E37 ; IC13.AG35 v2(61.15,47.17) ; IC13.AM35 61.31,50.77 v2(61.34,50.8) ; IC13.E36 59.95,29.17 v2(60.35,29.56) 59.95,29.96 IC13.F36
  TOP w0.381: IC13.N29 65.55,35.57 v2(65.15,35.96) 65.55,36.36 IC13.P29 65.55,36.37 v2(65.95,36.76) ; 74.93,29.59 75.15,29.37 IC13.D17 IC13.C17 ; IC13.U28 66.35,38.77 v2(66.75,39.17) ; IC13.W29 v2(65.95,39.97) ; v2(66.75,40.77) 66.35,40.37 IC13.W28 ; IC13.K37 IC13.K36 59.95,33.17 v2(60.35,33.56) ; v2(61.59,37.56) 61.22,37.56 60.81,37.97 IC13.T35 ; 61.98,30.35 61.59,29.97 IC13.F34 61.55,29.96 v2(61.15,29.56) 60.76,29.17 IC13.E35 ; IC13.E37 IC13.E38 ; IC13.Y29 65.55,41.17 v2(65.95,41.57) ; v2(66.75,38.36) 66.35,37.97 IC13.T28 ; IC13.AD36 v2(60.35,44.77) 60.75,44.37 IC13.AD35 ; IC13.U29 65.55,38.77 v2(65.95,38.36) ; IC13.C30 64.75,27.57 v2(64.35,27.96) ; IC13.L24 69.55,33.96 v2(69.95,34.36) ; IC13.K26 v2(67.55,33.57) ; 72.75,33.97 IC13.L20 72.75,33.96 v2(72.35,33.56) 72.75,33.17 IC13.K20 72.75,33.16 ; v2(65.15,38.36) 65.55,37.97 IC13.T29 ; IC13.M28 66.35,34.77 v2(66.75,35.16) ; IC13.F35 60.75,29.97 v2(61.15,30.36) ; IC13.K35 60.75,33.16 v2(61.15,32.76) 61.97,32.76 ; IC13.K24 69.55,33.17 v2(69.95,32.76) 70.35,33.16 IC13.K23 ; IC13.M36 59.95,34.76 v2(60.35,34.36) ; IC13.E36 59.95,29.17 v2(59.55,29.56) ; IC13.K27 67.15,33.17 v2(66.75,33.56) 67.15,33.96 IC13.L27 ; IC13.E34 61.56,29.17 v2(61.95,29.56) 61.95,29.57 62.36,29.97 ; IC13.K21 71.95,33.16 v2(71.55,32.76) ; IC13.C20 72.9,27.71 72.9,28.22 IC13.D20 v2(72.36,28.76) ; IC13.M35 60.75,34.76 v2(61.15,34.36) ; IC13.M29 65.55,34.77 v2(65.15,35.16) ; v2(64.35,28.76) 64.75,28.37 IC13.D30
  TOP w0.406: 61.7,41.57 61.7,41.57 v2(61.15,41.57) ; v2(70.36,28.93) 70.36,29.59 ; IC13.T36 IC13.T35 ; v2(72.36,28.76) 72.36,29.68
  BOTTOM w0.381: v2(72.36,28.76) 72.24,28.88 C284.1 ; C283.1 v2(61.15,34.36) v2(60.35,34.36) v2(60.35,33.56) ; C293.1 68.44,36.77 R191.1 68.44,36.18 68.2,35.94 v2(67.82,35.94) ; C281.1 v2(66.75,33.56) ; v2(65.95,36.76) 66.04,36.85 C277.1 66.04,38.28 v2(65.95,38.36) ; R283.2 64.47,38.36 v2(65.15,38.36) ; C279.1 v2(72.35,33.56) ; v2(67.55,33.57) 67.55,33.25 C310.1 ; C276.1 66.04,40.05 v2(65.95,39.97) 66.04,39.88 C285.1 v2(66.75,39.17) ; C276.1 66.04,41.48 v2(65.95,41.57) ; C276.1 v2(66.75,40.77) ; v2(65.15,35.96) 64.75,36.36 C301.1 ; C302.1 v2(61.59,37.56) ; C314.1 R198.1 66.84,35.25 v2(66.75,35.16) ; C305.1 v2(65.15,35.16)
  BOTTOM w0.406: v1(62.29,50.86) C313.1 v1(63.5,49.78) ; v2(71.55,32.76) 71.6,32.71 C306.1 ; v2(69.95,34.36) 69.95,35.1 C291.1 ; R196.2 v2(65.02,30.35) ; C311.1 70.08,29.44 70.1,29.41 70.1,29.21 70.36,28.96 v2(70.36,28.93) ; v2(60.35,29.56) 60.35,29.08 C275.1 ; C298.1 62.67,28.85 v2(61.95,29.56) 62.31,29.92 C278.1 ; C304.1 61.09,41.63 v2(61.15,41.57) ; v2(61.15,32.76) 61.32,32.94 C295.1 ; v1(63.69,45.02) C296.1 v1(61.53,45.02) ; v2(61.15,29.56) 61.21,29.5 C280.1 ; C292.1 v2(64.39,49.15) ; v2(64.35,28.76) 64.35,29.15 C282.1 ; C300.1 60.35,45.52 v2(60.35,46.37) ; v2(60.35,44.77) 59.93,44.77 C303.1 ; C289.1 v1(73.91,30.4) ; C287.1 63.95,27.56 v2(64.35,27.96) ; C286.1 59.91,51.61 v2(60.35,51.17) ; C290.1 59.55,29.89 v2(59.55,29.56) 58.93,28.94 C299.1 ; v2(61.15,39.97) 60.96,40.16 C312.1
  BOTTOM w0.508: C280.1 C275.1 C299.1 ; v1(61.53,45.02) 61.28,44.77 v2(60.35,44.77)
  vias: v1(28.17,27.72) v1(28.17,26.96) v1(29.06,27.72) v1(29.06,26.96)
1V8A\G: length 4.8
  TOP w0.305: C134.1 25.15,86.74 24.87,86.47 IC8.2
  TOP w0.508: C114.1 28.26,86.74 C134.1
2V5\G: length 185.2
  TOP w0.406: C383.1 129.9,78.14 ; C384.1 131.17,78.14
  TOP w0.508: v1(90.78,64.05) v1(111.61,64.05) ; 132.59,71.88 132.59,70.74 133.48,69.85 R108.1 ; TP16.1 128.14,78.49 ; v1(90.53,22.64) 100.56,22.64 110.77,32.85 110.77,49.36 111.61,50.2 v1(111.61,60.62) ; 124.33,72.52 120.31,68.49 v1(111.61,68.49) ; R6.2 27.22,64.43 Q7.2 R86.2 28.3,60.19 v1(28.87,59.62)
  BOTTOM w0.508: v1(111.61,68.49) v1(111.61,64.05) v1(111.61,60.62) ; R178.1 v1(90.53,22.64) ; v1(90.78,64.05) 88.62,66.2 65.1,66.2 62.56,63.66 58.78,63.66 55.27,60.16 29.41,60.16 v1(28.87,59.62)
2V5_MOS\G: length 143.7
  TOP w0.508: v1(96.5,53.63) 96.5,48.68 95.61,47.79 v1(92.56,47.79) ; v1(103.39,71.31) L50.1 107.14,71.31 C417.2 109.19,71.25 C416.1 v1(110.08,71.28) ; v1(27.22,60.93) R6.1 ; Q7.3 v1(29.19,61.25)
  BOTTOM w0.508: L6.2 91.8,34.84 93.19,36.23 93.19,43.47 92.56,44.1 90.84,44.1 L34.1 L16.2 92.27,45.21 92.56,45.5 v1(92.56,47.79) ; v1(103.39,71.31) 100.71,71.31 96.5,67.09 64.72,67.09 62.18,64.55 58.52,64.55 54.94,60.97 29.46,60.97 v1(29.19,61.25) 28.87,60.93 v1(27.22,60.93) ; v1(110.08,71.28) 109.7,71.28 96.5,58.08 v1(96.5,53.63)
3V3\G: length 216.5
  TOP w0.406: R230.2 v1(79.73,20.36) ; v1(10.01,56.43) 10.01,55.79 v1(9.12,54.9) 9.12,31.91 10.52,30.52 v1(15.34,30.52) ; R84.2 33.5,61.38 ; C381.1 24.87,72.3 ; C382.1 26.14,72.43 ; v1(51.54,85.51) 51.54,79.41 ; R357.1 v1(75.92,7.28)
  TOP w0.508: v1(75.92,7.28) 78.72,7.28 v1(80.37,8.93) ; D5.1 94.72,10.45 93.19,8.93 v1(80.37,8.93) ; v1(80.37,8.93) 80.37,6.39 77.19,3.21 40.09,3.21 37.69,5.61 37.69,20.74 36.42,22.01 36.42,28.01 33.92,30.52 v1(15.34,30.52) ; R230.2 80.73,20.36 81.49,21.12 82.22,21.12 82.88,21.78 R43.2 83.34,22.08 83.67,22.41 R47.2
  BOTTOM w0.406: v1(51.54,85.51) R135.2 ; v1(79.73,20.36) 80.2,20.83 80.2,23.06 79.73,23.53 L7.2 ; R166.1 v1(15.34,30.52) ; R120.1 5.57,54.52 5.94,54.9 v1(9.12,54.9) ; v1(10.01,56.43) R68.1 11.15,57.31 11.41,57.57 11.41,60.36 18.26,67.22 v1(24.23,67.22)
  BOTTOM w0.508: v1(79.73,20.36) 79.73,20.23 78.84,19.34 78.84,10.2 v1(75.92,7.28)
  vias: v1(24.23,71.16) v1(24.23,70.4) v1(24.23,69.63) v1(24.23,68.87) v1(24.23,67.98) v1(24.99,71.16) v1(24.99,70.4) v1(24.99,69.63) v1(24.99,68.87) v1(24.99,67.98) v1(24.99,67.22) v1(33.38,62.01) v1(33.91,61.61) v1(34.54,62.36) v1(34.54,61.61) v1(50.65,79.03) v1(50.65,78.27) v1(51.41,79.03) v1(51.41,78.27) v1(52.17,79.03) v1(52.17,78.27)
3V3_MOS\G: length 275.2
  TOP w0.254: U1.9 95.28,76.66 v1(95.52,76.9) ; U1.20 99.31,74.73 v1(99.58,74.99) ; U1.30 101.77,77.66 v1(101.61,77.5) ; U1.48 95.81,82.79 95.51,83.1 v1(95.1,83.1)
  TOP w0.305: IC8.17 v1(21.87,79.4)
  TOP w0.356: IC13.AR26 67.95,53.17 67.55,52.77 v2(67.55,52.77) ; R475.1 v1(133.83,12.74) ; IC13.AD29 v2(65.95,43.97) 65.55,43.57 IC13.AC29 ; IC13.AC28 66.35,43.57 v2(66.75,43.97) IC13.AD28 ; v2(65.95,45.57) IC13.AF29 ; v2(80.35,27.96) 80.75,27.57 IC13.C10 ; IC13.E5 84.35,28.77 v2(84.35,28.76)
  TOP w0.381: IC13.AP6 83.95,52.36 83.57,51.98 v2(83.57,51.82) ; IC13.K13 78.35,33.17 v2(78.75,32.76) 79.15,33.16 IC13.K12 ; IC13.L13 v2(78.75,33.56) ; v2(85.95,43.17) 86.35,43.56 IC13.AC3 ; IC13.AF10 80.76,45.97 v2(81.15,46.37) ; v2(81.15,44.77) 80.76,44.37 IC13.AD10 ; IC13.AD11 79.96,44.37 v2(80.35,44.77) ; v2(80.35,47.17) 79.96,46.77 IC13.AG11 ; v2(65.95,46.37) IC13.AF28 ; IC13.AC4 85.55,43.56 v2(85.15,43.17) ; IC13.AR19 73.55,53.09 v2(73.15,52.69) ; IC13.AJ21 71.95,48.37 v2(71.55,48.77) 71.15,48.37 IC13.AJ22 ; IC13.AU31 v2(63.55,55.17) ; v2(66.75,47.97) IC13.AH27 ; IC13.AP35 v2(60.35,52.77) ; IC13.AH18 74.35,47.57 v2(74.75,47.97) IC13.AJ18 ; v2(85.15,51.97) 84.75,52.37 IC13.AP5 ; IC13.AJ27 67.15,48.37 v2(67.55,48.77) IC13.AJ26 ; v2(65.15,47.17) IC13.AG29 ; IC13.F3 86.35,29.97 85.95,30.36 v2(85.95,30.36) ; IC13.D13 78.35,28.69 v2(78.75,29.09) ; IC13.AN35 v2(60.35,51.97) ; v2(63.55,53.57) IC13.AR31 ; v2(85.95,29.56) IC13.F4 ; v2(65.95,48.77) IC13.AJ28 ; IC13.F5 84.76,29.97 v2(85.15,30.36) ; IC13.AG10 80.76,46.77 v2(81.15,47.17) ; v2(63.55,54.37) IC13.AT31 ; v2(61.95,51.97) IC13.AP34 ; IC13.U3 v2(85.95,38.37) ; IC13.L11 v2(80.35,33.56) IC13.K10 ; IC13.AH26 67.95,47.57 v2(68.35,47.97) ; v2(80.35,38.36) IC13.U11 ; IC13.AH21 v2(71.55,47.97) ; IC13.M11 79.95,34.77 v2(80.35,34.36) IC13.L10 ; v2(77.95,29.09) 77.55,28.69 IC13.D14 ; IC13.AF11 79.96,45.97 v2(80.35,46.37) ; IC13.V11 v2(80.35,39.17) IC13.U10 ; IC13.AH22 v2(71.55,47.17) ; IC13.U4 v2(85.15,38.37)
  TOP w0.406: R52.2 v1(91.03,30.9) ; R37.2 93.8,46.11 v1(93.27,46.65) ; R225.2 49.11,55.54 v1(48.51,56.13) ; R41.2 v1(97,41.19) ; R101.2 v1(64.34,74.61) ; R586.1 v1(92.72,69) ; IC13.AV31 v2(63.55,55.97) ; v1(85.21,22.64) 85.32,22.64 85.95,22.01 R99.2 ; R609.1 v1(154.41,36.16) ; C144.1 101.22,50.19 v1(101.45,49.95) ; R293.2 v1(91.52,24.04) ; R38.2 v1(97,43.47) ; R314.1 v1(17.02,82.3) ; v1(121.67,103.54) R606.1 R605.1 ; R222.2 v1(91.03,29.76) ; R49.2 v1(91.03,28.61) ; IC13.D10 v2(81.15,27.96) ; R45.2 v1(85.99,58.55) ; v1(55.88,56.44) R233.2 ; R94.2 v1(102.59,35.09) ; R91.2 v1(102.59,36.23) ; R223.2 v1(89.26,22.77) ; R298.2 v1(31.62,88.65) ; R244.2 77.25,23.37 77.25,21.44 77.55,21.14 R248.2 R245.2 79.03,20.04 79.6,19.47 v1(81.26,19.47) ; R54.2 v1(91.03,27.47) ; R111.2 v1(64.26,70.8) ; R608.1 v1(151.56,36.16) ; R39.2 v1(97,42.33) ; R313.1 v1(17.02,79.5) ; R224.2 v1(57.15,59.98) ; R96.2 v1(102.59,37.38) ; R118.2 v1(30.07,82.08) ; U11.8 v1(89.92,57.21)
  TOP w0.508: v1(17.5,40.26) v1(17.5,49.43)
  TOP w0.762: v3(34.27,76.62) 34.27,77.63 31.47,80.43 31.09,80.43 30.85,80.66 v3(30.85,80.67) 30.85,80.7 31.04,80.89 LED5.1
  BOTTOM w0.305: C209.1 101.45,30.77 IC2.37 ; IC2.12 v1(101.45,49.95)
  BOTTOM w0.356: C4.1 62.14,56.87 61.63,57.38 58.64,57.38 57.7,56.44 v1(55.88,56.44) 54.94,55.5 49.15,55.5 v1(48.51,56.13)
  BOTTOM w0.406: C408.1 101.62,77.51 v1(101.61,77.5) ; C154.1 74.67,48.05 v2(74.75,47.97) ; v2(63.55,53.57) 63.58,53.59 C142.1 ; C132.1 73.5,53.03 v2(73.15,52.69) ; v2(71.55,48.77) v2(71.55,47.97) ; v2(71.55,47.97) 71.47,48.05 C130.1 ; v2(71.55,47.97) v2(71.55,47.17) ; v1(100.41,78.26) C407.2 v1(100.41,80.35) ; R83.2 86.36,38.77 v2(85.95,38.37) 86.85,37.47 C1.1 ; R589.1 v1(99.57,80.33) ; v2(81.15,27.96) 81.66,27.46 C106.1 ; v2(63.55,54.37) 63.46,54.46 C131.1 ; v2(80.35,39.17) 80.75,39.57 C133.1 ; C208.1 v1(102.72,52.74) ; C128.1 v2(80.35,34.36) ; C125.1 v2(61.95,51.97) 61.7,51.71 C150.1 60.6,51.71 v2(60.35,51.97) v2(60.35,52.77) ; R615.1 R614.1 v1(101.19,121.45) ; C139.1 v2(85.15,51.97) ; v2(66.75,47.97) 66.67,48.05 C156.1 v2(65.95,48.77) ; v2(84.35,28.76) 84.33,28.74 C15.1 ; v2(67.55,48.77) C147.1 68.27,48.05 v2(68.35,47.97) ; v2(63.55,55.97) 63.32,56.2 62.17,56.2 C4.1 62.14,55.85 62.83,55.17 v2(63.55,55.17) ; v2(67.55,52.77) 66.8,52.77 66.27,52.24 C138.1 ; v2(65.15,47.17) 65.07,47.08 C22.1 ; v2(85.95,43.17) 86.16,43.17 86.67,43.68 C122.1 ; v2(80.35,27.96) 80.49,27.82 R251.2 ; C149.2 v1(22.99,78.87) ; v2(81.15,44.77) 81.15,45.25 C135.1 81.47,46.37 v2(81.15,46.37) ; v1(95.52,76.9) 95.11,77.3 C411.1 ; L21.1 83.03,49.85 v2(83.55,50.37) ; v1(103.1,29.88) 102.97,30.01 C209.1 ; R97.2 v1(98.91,56.04) ; C409.1 99.61,74.97 v1(99.58,74.99) ; R144.2 v1(98.81,28.51) ; v2(78.75,32.76) 78.91,32.92 C39.2 ; R611.1 v1(149.07,36.61) ; v1(14.99,92.71) 14.99,92.08 L19.1 14.35,91.95 v1(14.35,92.71) ; C12.1 65.81,45.71 v2(65.95,45.57) ; C410.1 95.26,83.1 v1(95.1,83.1) ; R168.2 v1(94.21,55.16) ; C155.1 65.41,44.51 v2(65.95,43.97) ; C38.1 78.08,28.97 v2(77.95,29.09) ; v1(93.93,81.17) C406.2 v1(95.01,82.23) ; v2(85.95,29.56) 86.33,29.56 C5.2 86.06,30.26 v2(85.95,30.36) ; L23.2 85.92,51.93 v2(85.95,51.97) ; R139.1 R138.2 v1(103.99,56.04) ; R98.2 v1(100.18,56.04) ; R612.1 v1(154.28,33.59) ; R167.2 v1(90.88,54.04) ; v2(80.35,47.17) v2(81.15,47.17) C145.1 ; L22.1 74.83,54.99 v2(74.7,55.12) 74.04,55.78 74.04,57.89 73.64,58.29 L36.1 ; R170.2 90.17,57.47 v1(89.92,57.21) 89.92,57.82 R170.2
  BOTTOM w0.508: R153.2 v1(17.5,40.26) ; v1(103.89,18.8) 109.6,13.08 133.49,13.08 v1(133.83,12.74) ; v3(34.27,65.57) 33.34,64.64 25.91,64.64 23.88,62.61 23.88,58.67 17.5,52.29 v1(17.5,49.43)
  BOTTOM w0.762: v3(34.27,65.57) v3(34.27,76.62)
  BOTTOM w1.524: 112.65,33.53 111.63,33.53 104.39,26.29 v4(101.98,26.29)
  vias: v1(22.99,79.5) v1(23.22,78.02) v1(23.98,78.02)
3V3A_E\G: length 35.8
  TOP w0.305: v1(24.26,86.11) 24.37,85.99 IC8.3
  BOTTOM w0.508: C137.2 24.13,86.23 v1(24.26,86.11) ; C137.2 24.13,88.39 ; C137.2 18.03,87.12 17.08,88.07 C136.2 17.14,89.34 L19.2 17.02,91.82 C153.2 TR2.2 ; 24.13,88.39 24.13,88.77 23.62,89.28 U17.5 ; 24.13,88.39 28.66,88.39 29.72,89.45 C160.2 TR2.7
5V0\G: length 346.6
  TOP w0.406: R509.1 v1(152.25,5.97) ; R78.2 30.46,56.43 ; R255.2 103.9,100.4
  TOP w0.508: R119.1 v1(145.9,5.97)
  TOP w0.762: 104.88,99.73 108.31,96.3 108.31,86.91 v3(109.45,85.76)
  TOP w1.016: v3(119.76,101.89) L12.2
  BOTTOM w0.508: v3(25.5,58.33) 25.12,58.33 19.28,52.49 19.28,44.36 10.52,35.6 10.52,19.72 13.06,17.18 13.06,8.29 14.45,6.9 14.46,6.9 14.83,6.52 14.83,6.51 19.28,2.07 78.33,2.07 83.8,7.53 128.5,7.53 129.39,8.42 140.44,8.42 142.89,5.97 v1(145.9,5.97) v1(152.25,5.97)
  BOTTOM w1.016: v3(119.76,101.89) v3(103.86,101.89) 93.45,101.89 75.92,84.37 47.98,84.37 46.58,82.97 46.58,73.82 42.9,70.14 42.9,66.33 39.85,63.28 26.52,63.28 25.5,62.27 v3(25.5,58.33)
5V0_MOS\G: length 501.7
  TOP w0.279: XP1.18 v1(48.5,117.49)
  TOP w0.381: v1(98.53,118.66) 98.91,118.66 99.49,118.08 U8.7
  TOP w0.406: C429.1 156.31,41.82 ; C123.2 v1(29.46,116.59) ; C426.1 v1(131.7,104.01)
  TOP w0.508: R140.2 R141.2 47.94,113.35 D20.2 v1(50.1,113.35) ; v1(29.46,116.59) 30.32,116.59 ; v1(153.39,7.53) 141.71,7.53 135.87,13.37 125.2,13.37 124.69,12.86 v1(124.69,11.47) 119.48,11.47 R474.1 118.97,12.36 118.59,12.74 111.35,12.74 110.59,13.5 110.59,17.82 109.96,18.45 105.51,18.45 105,17.94 R368.2 ; v1(58.27,81.19) 54.84,84.62 54.84,92.62 34.39,113.07 32.74,113.07 29.95,115.86 ; v1(36.81,61.63) 36.81,59.35 35.7,58.24 Q5.3 33.44,57.44 R4.1 33.44,54.08 32.56,53.2 30.03,53.2 28.93,52.1 28.93,33.06 28.17,32.3 15.6,32.3 14.52,33.37 v1(14.52,35.15)
  TOP w1.016: 158.09,36.11 v3(165.63,36.11)
  BOTTOM w0.406: v1(154.03,40.93) 153.33,40.93 R633.2 153.39,41.63 v1(154.03,41.63) ; U3.5 116.46,107.96 117.96,106.46 ; v1(150.22,33.06) 150.24,33.03 C433.1 ; U4.5 v1(158.85,38.77) ; C437.1 v1(96.6,116.85)
  BOTTOM w0.508: v1(29.46,116.59) 37.78,116.59 39.85,118.66 47.33,118.66 v1(48.5,117.49) 48.54,117.45 C251.1 50.06,117.45 50.8,116.71 50.8,113.41 50.74,113.35 ; R165.2 Q9.2 15.79,35.22 R8.2 v1(14.52,35.15) ; R472.1 v1(124.69,11.47) ; v1(50.1,113.35) 50.74,113.35 ; 50.74,113.35 50.93,113.16 50.93,110.74 ; v1(58.27,81.19) 58.27,65.44 54.46,61.63 v1(36.81,61.63) ; 149.84,30.9 149.84,21.37 156.57,14.64 156.57,8.67 155.42,7.53 v1(153.39,7.53) ; U14.5 50.93,110.74 ; 50.93,110.74 v3(52.96,110.74)
  BOTTOM w0.762: v3(132.97,105.54) 132.04,106.46 102.72,106.46 101.45,107.73 101.45,111.82 C438.1 92.07,108.75 86.21,108.75 83.41,105.96 v3(83.41,94.91) 67.27,94.91 62.46,99.72 R174.1 60.76,102.4 52.96,110.2 v3(52.96,110.74)
  BOTTOM w1.016: v3(165.63,36.11) 165.84,36.31 165.84,94.53 162.41,97.95 157.71,97.95 155.42,100.24 147.55,100.24 142.25,105.54 v3(132.97,105.54)
  vias: v1(96.5,115.61) v1(96.5,114.85)
5V0_VBUS0\G: length 125.2
  TOP w0.406: C78.2 97.73,100.46
  TOP w0.762: L55.2 151.65,19.43 141.1,29.98 141.1,61.61 139.17,63.54 v3(123.17,63.54) ; v3(116.05,97.45) v3(116.05,70.52)
  BOTTOM w0.762: v3(123.17,63.54) 116.18,70.52 v3(116.05,70.52) ; v3(97.64,97.45) v3(116.05,97.45)
5V0_VBUS1\G: length 69.5
  TOP w0.762: L56.2 145.17,59.82 v3(145.16,59.82) ; v3(114.28,73.82) v3(114.28,70.52)
  BOTTOM w0.762: v3(145.16,59.82) 142.75,62.23 122.44,62.23 114.4,70.27 114.4,70.4 v3(114.28,70.52) ; R110.2 105,83.45 106.45,82 106.45,77.96 110.72,73.7 114.15,73.7 v3(114.28,73.82)
5V_VIDEO\G: length 14.9
  TOP w0.508: D16.2 87.99,102.61 C102.1 87.99,99.37 C84.1 87.73,99.08 L41.1 93.49,96.56 v1(93.79,96.26) IC9.4
  BOTTOM w0.508: v1(93.79,96.26) 93.83,96.3 C176.1
12V\G: length 35.9
  TOP w0.406: 155.57,72.77 155.57,69.6 155.19,69.22 R123.2 ; C52.2 v1(23.98,6.26) ; C44.2 153.03,73.53 ; C80.2 154.31,73.53 ; C127.2 132.33,89.79 ; C121.2 133.6,89.79 ; R100.1 v1(126.59,98.17)
  TOP w0.508: 22.48,4.19 22.82,3.85 23.51,3.85 23.52,3.85 24.44,3.85 24.44,3.85 27.1,3.85 R51.2
  BOTTOM w0.406: v1(126.59,98.17) 134.25,98.17 135.1,97.32 v1(135.1,89.95) ; C50.2 v1(16,46.49) ; R124.2 v1(12.55,59.73) ; C112.2 v1(13.84,58.18) ; C81.2 v1(41.38,93.26) ; v1(50.14,85.51) R134.2
  vias: v1(11.53,47.79) v1(11.53,47.03) v1(11.53,46.27) v1(13.18,47.79) v1(13.95,47.79) v1(14.71,47.79) v1(21.57,6.51) v1(21.57,5.63) v1(21.57,4.74) v1(22.33,6.51) v1(22.33,5.63) v1(22.33,4.74) v1(23.09,6.51) v1(23.09,5.63) v1(23.09,4.74) v1(39.6,92.75) v1(39.6,92.11) v1(39.6,91.48) v1(40.36,92.75) v1(40.36,92.11) v1(40.36,91.48) v1(41,92.57) v1(41.63,92.57) v1(133.58,87.03) v1(133.58,86.14) v1(133.58,85.25) v1(134.47,87.03) v1(134.47,86.14) v1(134.47,85.25) v1(135.36,87.03) v1(135.36,86.14) v1(135.36,85.25) v1(136.25,87.03) v1(136.25,86.14) v1(136.25,85.25) v1(149.86,74.55) v1(149.86,73.79) v1(150.62,74.55) v1(150.62,73.79) v1(151.38,74.55) v1(151.38,73.79) v1(152.15,74.55) v1(152.15,73.79)
+1V2: length 41.2
  TOP w0.203: U18.12 118.96,44.41 118.88,44.48 ; U18.7 119.24,46.41 118.85,46.01 118.31,46.01 C328.1 ; v1(128.37,49.46) 128.37,49.31 127.86,48.81 U18.51 ; v1(126.44,48.68) U18.53 ; U18.64 v1(122.04,48.68) ; U18.61 v1(123.24,48.68) ; U18.67 v1(120.84,48.68)
  TOP w0.406: C328.1 118.7,45.38 v1(118.85,45.38) 118.21,44.74 C331.1 118.45,44.48 118.88,44.48
  TOP w0.508: v1(126.44,48.68) v1(123.24,48.68) v1(122.04,48.68) v1(120.84,48.68)
  BOTTOM w0.381: v1(118.85,45.38) 118.85,43.6 121.01,41.44 FB1.2
  BOTTOM w0.406: v1(126.44,48.68) 126.47,48.71 C360.1 ; C318.1 122.02,48.69 v1(122.04,48.68) ; C321.1 C317.1 120.88,48.72 v1(120.84,48.68) ; C254.1 123.29,48.73 v1(123.24,48.68) ; R348.1 v1(111.86,45) ; C335.1 v1(111.86,46.14)
  BOTTOM w0.508: v1(120.84,48.68) 119.23,48.68 118.85,48.3 v1(118.85,45.38) 118.21,45.38 117.7,44.87 R318.1 ; C343.1 v1(128.37,49.46) ; C343.1 127.61,47.92 128.14,47.38 R352.1 ; C343.1 C360.1
  vias: v1(111.74,47.03) v1(112.37,47.03)
+1V2A: length 3.6
  TOP w0.406: R346.2 137.83,52.93 C319.2 U24.2
GND: length 2487.6
  TOP w0.152: 63.49,31.71 63.91,32.13
  TOP w0.203: v1(118.34,42.41) U18.17
  TOP w0.254: v2(68.54,56.63) 68.5,56.67 v1(68.5,61.38) v1(68.5,63.03) v1(68.5,65.28) 68.5,74.43 v1(64.92,78.01) 55.6,87.33 v1(55.6,88.13) 55.6,92.99 v1(52.2,96.39) v1(43.12,105.47) 39.75,108.84 v1(39.75,116.59) ; v1(70.94,57.15) v1(70.94,61.38) v1(70.94,63.03) 70.94,77.54 v1(68.75,79.74) v1(66.04,82.45) 59.59,88.9 v1(59.59,90.82) 59.59,92.57 v1(56.81,95.35) v1(44.96,107.19) 43.54,108.62 ; 43.54,108.62 v1(43.54,110.24) 43.54,112.31 42.61,113.23 42.61,117.16 v1(42.67,117.22) ; 43.54,108.62 42.29,109.87 v1(42.29,109.98) ; XS5.6 120.13,109.8 114.62,104.3 v1(114.62,89.92) v1(114.62,79.92) 114.62,76.2 111.74,73.32 v1(108.18,73.32) ; v1(143.23,62.99) v1(143.23,47.15) v1(143.23,34.96) v1(143.23,32.8) 146.41,29.63 v1(146.41,29.37) 149.45,26.33 v1(154.92,26.33) ; v1(143.23,62.99) 143.38,62.99 154.01,52.36 v1(154.94,52.36) 156.31,52.36 v1(156.57,52.11) ; v1(143.23,62.99) 143.23,63.14 140.17,66.2 v1(115.32,66.2) v1(102.46,66.2) 86.72,66.2 85.95,65.44 v1(85.95,65.28) 85.95,63.41 86.34,63.03 v1(87.99,63.03) 89.79,64.83 v1(96.62,64.83) v1(115.44,64.83) 139.14,64.83 141.86,62.11 v1(141.86,47.15) 141.86,31.13 v1(144.82,28.17) 148.42,24.57 v1(154.92,24.57) ; v1(74.66,57.28) 74.66,57.3 74.65,57.3 v1(74.65,61.38) v1(74.65,63.03) v1(74.65,65.28) 74.65,80.33 66.17,88.81 v1(66.17,89.8) 66.17,92.09 v1(49.12,109.13) ; v1(110.59,59.85) 109.85,60.6 109.3,60.6 ; v1(122.85,58.25) 122.91,58.19 v1(122.91,56.04) ; v1(99.04,71.28) v1(99.04,68.49) ; v1(93.27,33.82) 93.45,33.82 95.57,31.7 105.07,31.7 v1(108,34.63) 108.61,35.24 v1(108.61,38.39) v1(108.61,40.68) v1(108.61,52.36) v1(108.61,55.49) 108.61,59.9 109.3,60.6 ; v1(46.23,112.52) 46.23,111.25 46.74,110.74 v1(46.86,110.74) 46.8,110.68 46.8,109.41 v1(48.01,108.2) v1(59.28,96.93) 64.95,91.26 v1(64.95,89.75) 64.95,88.08 v1(71.2,81.83) 73.38,79.65 v1(73.38,65.28) ; v1(51.82,112.9) v1(51.82,108.93) 51.82,108.32 v1(62.61,97.52) 67.44,92.7 v1(67.44,90.05) 67.44,89.42 76.18,80.68 v1(76.18,78.52) v1(76.18,65.28) v1(76.18,63.03) v1(76.18,61.38) ; v1(107.39,58.2) 106.58,58.2 v1(105.79,57.42) 105.61,57.24 105.61,42.61 v1(105.64,42.58) 105.64,35.85 v1(104.5,34.71) 103.94,34.15 96.49,34.15 93.71,36.93 90.21,36.93 90.02,36.74 v1(90.02,36.44) ; v1(107.39,58.2) v1(107.39,45.5) 107.39,35.76 106.84,35.22 v1(106.05,34.42) 104.56,32.93 104.18,32.93 v1(102.21,32.93) 95.99,32.93 93.83,35.09 v1(93.07,35.09) ; v1(107.39,58.2) 107.39,60.84 v1(108.56,62.01) 108.56,62.02 109.56,63.03 119.04,63.03 119.42,63.03 119.42,63.03 v1(122.91,59.54) ; v1(156.44,55.03) 153.38,55.03 v1(152.4,56.01) 152.4,56.13 v1(147.13,61.4) 140.93,67.6 v1(125.98,67.6) v1(115.19,67.6) v1(102.46,67.6) 101.7,67.6 101.07,68.24 v1(101.07,72.17) 100.81,72.43 U1.23 ; v1(120.88,56.01) v1(120.88,58.2) 120.88,59.6 118.72,61.76 110.47,61.76 109.3,60.6 ; U1.2 95.48,80.16 v1(95.52,80.2) ; v1(107.8,81.95) 109.7,81.95 111.86,84.11 v1(111.86,96.18) 111.86,106.46 115.42,110.02 v1(115.42,110.07) 115.42,111.42 114.66,112.18 114.66,114.08 114.91,114.34 116.43,114.34 116.66,114.11 116.71,114.06 v1(116.71,113.6) 116.9,113.41 116.9,110.31 v1(117.07,110.15) 117.07,109.21 113.23,105.37 v1(113.23,82.84) v1(113.23,79.92) 113.23,78.24 v1(112.12,77.13) 110.34,75.35 v1(107.8,75.35) ; v1(111.61,79.92) 111.61,79.79 111.48,79.92 v1(107.93,79.92) ; 73.38,59.99 73.38,59.97 73.39,59.96 v1(73.39,57.71) ; v1(72.16,57.7) v1(72.16,61.38) v1(72.16,63.03) v1(72.16,65.28) 72.16,78.6 v1(69.19,81.57) 62.15,88.61 v1(62.15,90) 62.15,92.02 v1(58.14,96.04) v1(46.55,107.63) 44.96,109.22 44.96,112.74 44.45,113.25 44.45,115.57 44.32,115.7 v1(44.32,115.82) ; v1(93.32,31.41) 94.08,31.41 95.01,30.48 105.73,30.48 v1(109.13,33.88) 110.16,34.91 v1(110.16,49.69) v1(110.16,54.86) 110.16,58.15 v1(110.21,58.2) ; v1(41.27,113.67) 41.03,113.42 41.03,109.35 v1(44.07,106.3) v1(55.66,94.72) 58.01,92.37 v1(58.01,89.62) 58.01,87.63 v1(63.55,82.09) v1(67.33,78.31) 69.72,75.92 v1(69.72,63.03) v1(69.72,61.38) v1(69.72,57.4) v1(69.72,56.77) 69.75,56.74 69.75,54.57 v2(69.95,54.37) ; IC13.AJ35 60.69,48.42 60.01,48.42 IC13.AJ36 ; v1(103.96,80.69) 103.93,80.66 U1.36 ; U1.42 v1(98.81,80.97)
  TOP w0.279: XP1.8 v1(43.5,121.16) ; XP1.2 v1(40.5,121.16) ; XP1.11 v1(45,121.16) ; XP1.17 v1(48,121.16) ; XP1.5 v1(42,121.16)
  TOP w0.305: U22.4 v1(72.11,103.67) ; IC8.1 25.37,85.95 v1(25.53,86.11) ; 73.38,59.99 v1(73.38,61.38) v1(73.38,63.03) v1(73.38,65.28) ; v1(103.99,76.16) U1.27 ; U22.1 v1(72.11,101.72) ; U22.10 v1(68.41,104.32) ; U22.14 v1(68.43,101.72)
  TOP w0.356: v2(88.37,25.56) 87.96,25.97 IC13.A1 ; U9.P9 v2(34.12,45.4) ; v2(68.35,33.56) 68.75,33.17 IC13.K25 ; U9.M9 33.36,44.2 v2(33.12,44.44) ; IC13.P2 IC13.P1 88.54,36.37 v2(88.54,36.36) ; U10.D1 v2(52.52,15.41) ; v2(50.92,13.81) 51.31,14.21 U10.E2 ; v1(48.36,93.57) R55.1 v1(50.65,93.57) ; v2(51.72,9.01) 51.32,9.41 U10.E8 ; v2(34.92,37.4) 35.32,37.8 U9.D8 ; IC13.AB37 IC13.AB38 57.98,42.77 57.68,43.06 v2(57.53,43.06) ; IC13.AC36 59.95,43.57 v2(60.35,43.97) ; IC13.AK4 85.56,49.17 v2(85.95,49.57) ; U9.M1 41.48,44.2 v2(41.49,44.19) ; IC13.T10 80.75,37.96 v2(80.35,37.56) ; U9.G1 41.64,40.2 v2(41.66,40.19) ; U9.T1 v2(42.09,47.4) ; U6.3 v1(154.13,38.22) ; v2(76.35,38.36) 76.75,38.76 76.75,38.77 ; v2(41.32,35.8) 41.28,35.84 41.28,35.84 U9.B1 ; v2(65.95,32.76) 66.35,33.16 IC13.K28 ; v2(41.53,37.54) 41.18,37.54 U9.D1 ; v2(33.9,39.4) 33.91,39.4 U9.F9 ; U9.B3 39.32,36.2 v2(39.72,35.8) ; C90.2 v1(53.44,91.1) ; U10.E1 51.3,15.03 v2(51.3,15.65) ; v2(34.92,38.2) 35.32,38.6 U9.E8 ; v2(44.13,15.62) 44.13,15.49 44.11,15.48 U10.P1 ; v2(70.75,27.16) 71.15,26.77 IC13.B22 ; v2(61.95,28.76) 61.56,28.37 IC13.D34 IC13.C34 ; v2(49.71,8) U10.G9 U10.G8 ; v2(76.35,29.09) 76.35,29.09 75.95,28.7 IC13.D16 ; U9.G8 U9.G9 33.98,40.2 33.98,40.2 v2(33.91,40.2) ; v2(64.35,27.16) 63.96,26.77 IC13.B31 ; v2(45.71,15.66) 45.71,15.66 U10.M1 ; v2(70.75,27.96) 71.15,27.57 IC13.C22 ; v2(50.51,8) 50.54,8.03 50.54,8.59 U10.F9 ; U10.B3 v2(53.32,13.01) ; v2(85.95,36.76) 85.56,36.37 IC13.P4 ; v2(60.35,43.17) 60.75,43.57 IC13.AC35 ; IC13.A8 IC13.B8 ; IC13.C28 v2(66.75,27.97) IC13.D28 ; IC13.AR12 79.15,53.16 v2(78.75,52.77) ; v2(54.12,15.41) 53.72,15.01 U10.B1 ; U9.E2 U9.E1 41.19,38.6 41.2,38.59 41.48,38.59 v2(41.53,38.54) ; v2(71.55,28.76) 71.55,28.76 IC13.D22 ; v2(77.95,52.77) 78.35,53.16 IC13.AR13 ; v2(63.95,25.06) IC13.A31 ; v2(41.49,45.8) 41.48,45.8 U9.P1 ; v2(61.47,48.39) 61.45,48.37 IC13.AJ35 ; v2(61.15,40.77) 60.75,40.37 IC13.W35 ; IC13.C7 83.16,27.57 v2(83.55,27.96) ; IC13.AT29 v2(65.95,53.57) ; IC13.AR23 v2(69.95,53.57) ; v2(61.15,27.16) 60.76,26.77 IC13.B35 IC13.A35 ; U10.D8 52.12,9.41 v2(52.52,9.01) ; U10.J8 48.11,9.41 v2(47.71,9.81) ; v2(77.15,53.57) 77.55,53.97 IC13.AT14 ; v1(123.44,104.01) 123.5,104.07 U5.3 ; IC13.L4 IC13.L3 ; v1(156.88,5.56) C307.2 v1(158.07,4.46) ; U9.T9 34.52,47.4 v2(34.12,47.8) ; U10.B9 53.72,8.61 v2(54.12,8.21) ; IC13.V25 68.75,39.57 v2(69.15,39.17) 69.55,39.56 IC13.V24 ; IC13.AJ23 70.35,48.37 v2(69.95,48.77) ; U10.A9 54.52,8.61 v2(54.92,8.21) ; IC13.AU37 v2(58.75,55.17) ; IC13.U21 v2(71.55,39.17) ; U10.G1 v2(49.71,15.61) ; v2(76.35,27.96) 76.75,27.57 IC13.C15 ; v2(69.15,27.97) IC13.D24
  TOP w0.381: IC13.AB18 74.35,42.76 v2(73.95,42.37) ; IC13.AB16 v2(76.35,42.37) ; v2(73.95,32.76) 73.55,33.17 IC13.K19 ; v2(78.75,27.96) 78.75,27.97 IC13.D12 ; IC13.R15 v2(76.35,37.56) 76.75,37.96 IC13.T15 ; IC13.AJ29 v2(65.15,48.77) ; IC13.AB24 v2(69.95,42.37) 69.55,41.97 IC13.AA24 ; IC13.AD15 76.75,44.36 v2(76.35,43.97) ; v2(85.95,40.77) 86.35,41.16 IC13.Y3 ; IC13.AA29 v2(65.15,41.57) ; IC13.W23 v2(70.75,39.97) 70.35,39.57 IC13.V23 ; v2(74.75,33.56) 74.36,33.17 IC13.K18 ; IC13.Y24 69.55,41.17 v2(69.95,40.77) 69.55,40.37 IC13.W24 ; IC13.U35 60.75,38.76 v2(61.15,38.36) ; IC13.AA15 76.76,41.97 v2(77.15,42.37) IC13.AB15 ; IC13.AH17 75.15,47.56 v2(74.75,47.17) ; IC13.AA20 v2(73.15,41.57) IC13.Y19 IC13.W19 ; IC13.L12 v2(79.55,33.56) ; IC13.N37 59.15,35.57 v2(59.55,35.96) 59.95,36.36 IC13.P36 ; IC13.R18 74.35,37.16 v2(73.95,36.76) ; IC13.AA17 75.15,41.96 v2(74.75,41.57) ; IC13.R24 69.55,37.16 v2(69.15,36.76) 68.76,36.37 IC13.P25 ; IC13.AR33 62.35,53.17 v2(62.75,52.77) ; IC13.AE25 68.75,45.17 v2(69.15,45.57) ; IC13.Y4 v2(85.15,41.57) ; v2(66.75,42.37) 66.35,41.97 IC13.AA28 ; IC13.AE2 87.15,45.17 v2(87.56,44.77) ; IC13.P35 60.76,36.37 61.21,36.82 v2(61.21,36.83) ; v2(65.15,34.36) 65.55,33.97 IC13.L29 ; v2(85.95,52.77) 85.56,52.37 IC13.AP4 ; v2(61.15,33.56) 60.75,33.96 IC13.L35 ; v2(85.95,43.97) 85.55,44.37 IC13.AD4 ; IC13.W21 IC13.V21 71.95,39.56 v2(71.55,39.17) 71.15,39.57 IC13.V22 ; IC13.W21 IC13.W20 ; IC13.W21 IC13.Y21 v2(71.55,41.57) IC13.AA22 ; IC13.W21 IC13.W22 ; IC13.L19 73.55,34.77 v2(73.15,35.16) ; IC13.U19 73.55,38.76 v2(73.15,38.36) 73.02,38.23 73.01,38.23 72.75,37.97 IC13.T20 ; IC13.W16 v2(76.35,39.97) 75.96,39.57 IC13.V16 ; v2(85.15,31.96) 85.16,31.96 IC13.H4 ; v2(85.15,31.16) 85.16,31.16 IC13.G4 ; v2(81.15,53.57) 80.75,53.97 IC13.AT10 ; v2(79.55,55.17) 79.95,54.77 IC13.AU11 ; IC13.AC20 72.75,43.57 v2(73.15,43.17) ; IC13.AR17 v2(74.75,53.57) ; v2(66.75,36.76) 66.35,36.37 IC13.P28 ; IC13.R21 IC13.R22 71.15,37.16 v2(70.75,36.76) ; IC13.U23 70.35,38.77 v2(70.75,38.36) 71.15,37.97 IC13.T22 ; IC13.E33 v2(62.75,29.57) ; v2(77.95,35.16) 77.95,34.37 IC13.L14 ; v2(42.55,15.62) 42.51,15.59 U10.T1 ; IC13.AD24 v2(69.95,43.97) 69.55,43.57 IC13.AC24 ; IC13.T16 75.95,37.96 v2(75.55,37.56) IC13.T17 ; IC13.AE21 71.95,45.17 v2(72.35,45.57) ; IC13.AA16 v2(75.55,42.37) ; v2(77.95,41.57) 77.56,41.17 IC13.Y14 ; IC13.AE18 74.35,45.17 v2(74.75,45.57) ; IC13.AT17 v2(74.75,54.37) ; IC13.AB17 75.15,42.76 v2(74.75,42.37) 74.35,41.97 IC13.AA18 ; IC13.AM3 86.36,50.77 v2(86.75,51.17) ; IC13.W14 77.56,40.37 v2(77.95,40.77) ; v2(77.95,43.17) 77.56,42.77 IC13.AB14 ; v2(70.75,43.17) 70.35,43.57 IC13.AC23 ; v2(76.35,40.77) 75.95,41.17 IC13.Y16 ; v2(79.55,27.96) 79.55,27.97 IC13.D11 ; IC13.AB22 v2(71.55,42.37) ; IC13.AH23 70.35,47.57 v2(69.95,47.17) ; IC13.AF2 87.15,45.97 v2(87.56,45.57) ; IC13.AC18 v2(74.75,43.17) ; v2(85.95,45.57) 86.35,45.96 IC13.AF3 ; IC13.AR7 83.15,53.16 v2(82.75,52.77) ; v2(74.75,34.36) 74.36,33.97 IC13.L18 ; v2(73.95,27.96) 73.95,27.97 73.95,27.97 IC13.D19 ; IC13.AJ19 73.55,48.37 v2(73.95,48.77) ; v2(79.55,52.77) 79.95,53.16 IC13.AR11 ; IC5.8 126.96,87.56 v1(127.23,87.29) 127.61,87.66 IC5.9 ; IC13.U17 75.15,38.77 v2(75.55,38.36) 75.95,38.76 IC13.U16 ; IC13.W20 IC13.W19 ; IC13.W20 IC13.Y20 v2(72.35,41.57) IC13.AA21 ; IC13.W20 IC13.V20 72.75,39.57 v2(73.15,39.17) 72.86,38.87 72.65,38.87 IC13.U20 ; v2(79.55,48.77) 79.15,48.37 IC13.AJ12 ; v2(65.15,36.76) 65.55,37.16 IC13.R29 ; v2(70.75,39.17) 71.15,38.77 IC13.U22 ; IC13.Y15 v2(77.15,40.77) ; v2(80.35,32.76) 79.95,33.17 IC13.K11 ; v2(69.95,47.97) 69.55,47.57 IC13.AH24 ; IC13.AR9 81.55,53.16 v2(81.15,52.77) ; v2(59.55,31.96) 59.56,31.96 59.95,31.57 IC13.H36 ; IC13.V15 76.76,39.57 v2(77.15,39.97) IC13.W15 ; IC13.AF4 85.55,45.96 v2(85.15,45.57) ; IC13.AD20 72.75,44.36 v2(72.35,43.97) ; IC13.AB11 80.35,43.17 v2(80.35,43.17) 80.75,43.56 IC13.AC10 ; v2(70.75,40.77) 70.35,41.17 IC13.Y23 ; IC13.AC15 v2(77.15,43.17) ; IC13.T19 73.56,37.97 v2(73.95,38.36) ; IC13.AD16 75.95,44.37 v2(76.35,44.77) ; IC13.AA25 v2(68.35,42.37) ; v2(73.95,35.96) 74.35,36.36 IC13.P18 ; IC13.R20 72.75,37.16 v2(72.35,36.76) ; IC13.AC22 71.15,43.57 v2(71.55,43.17) ; IC13.AM4 85.55,50.77 v2(85.95,50.37) ; IC13.AE28 66.35,45.17 v2(66.75,45.57) ; IC13.AH3 86.36,47.57 v2(86.75,47.97) ; IC13.AC21 71.95,43.57 v2(72.35,43.17) ; v2(68.35,33.56) 68.75,33.96 IC13.L25 ; v2(77.95,45.57) 77.56,45.17 IC13.AE14 ; v2(65.95,52.77) 65.95,52.77 IC13.AR28 ; IC13.AD23 70.35,44.37 v2(70.75,44.77) ; IC13.AE10 v2(80.35,45.57) ; IC13.V29 65.55,39.57 v2(65.15,39.97) ; IC13.AH13 78.35,47.57 v2(78.75,47.97) ; v2(77.15,29.09) 76.75,28.69 IC13.D15 ; IC13.R17 75.15,37.16 v2(74.75,36.76) ; IC13.AD17 75.15,44.36 v2(74.75,43.97) ; IC13.W19 IC13.W18 ; IC13.W19 IC13.V19 73.55,39.57 v2(73.95,39.17) ; IC13.U15 76.75,38.77 IC13.T14 ; IC13.AR20 72.75,53.17 v2(72.35,52.77) ; IC13.AB23 v2(70.75,42.37) ; U8.3 v1(98.84,122.34) ; v2(80.35,35.96) 79.96,35.57 IC13.N11 ; IC5.5 128.26,95.36 v1(128.27,95.38) ; v2(75.55,36.76) 75.95,37.16 IC13.R16 ; v2(65.15,46.37) 65.03,46.25 65.03,45.68 IC13.AE29 ; v2(73.95,43.97) 73.55,43.57 IC13.AC19 ; IC13.W18 IC13.W17 ; IC13.W18 IC13.V18 74.35,39.57 v2(74.75,39.17) ; IC13.W18 IC13.Y18 v2(73.95,41.57) IC13.AA19 ; v2(78.75,47.17) 79.15,47.56 IC13.AH12 ; IC13.U24 69.55,38.77 v2(69.95,38.36) 69.55,37.97 IC13.T24 ; IC13.H35 61.15,31.17 v2(61.15,31.16) ; IC13.K1 87.95,33.16 v2(87.56,32.76) ; v2(75.55,39.17) 75.15,39.57 IC13.V17 ; IC13.U18 74.35,38.77 v2(74.75,38.36) ; IC13.K2 87.16,33.17 v2(87.56,33.56) ; v2(60.35,30.36) 60.75,30.76 IC13.G35 ; IC13.P3 86.35,36.37 v2(85.95,36.76) ; IC13.AU8 82.35,54.77 v2(82.75,54.37) 83.15,53.97 IC13.AT7 ; IC13.Y22 v2(70.75,41.57) IC13.AA23 ; v2(84.35,51.97) 84.75,51.57 IC13.AN5 ; v2(63.55,52.77) 63.15,53.17 IC13.AR32 ; v2(85.95,35.96) 85.95,35.96 IC13.N4 ; IC13.T21 v2(71.55,38.36) ; v2(86.75,50.37) 86.36,49.97 IC13.AL3 ; IC13.AC16 v2(76.35,43.17) ; IC13.AD3 86.36,44.37 v2(86.75,44.77) ; v2(68.35,52.77) 68.35,52.77 IC13.AR25 ; IC13.AJ24 69.55,48.37 v2(69.95,48.77) ; IC13.T18 v2(74.75,37.56) ; IC13.AH29 v2(65.15,47.97) ; IC13.AU13 78.35,54.77 v2(78.75,55.17) ; IC13.AG28 v2(66.75,46.37) ; v2(70.75,43.97) 71.15,44.36 IC13.AD22 ; IC13.AP33 v2(61.95,52.77) ; IC13.AB20 v2(73.15,42.37) ; IC13.AH4 v2(85.15,47.97) ; v2(73.95,37.56) 73.56,37.17 IC13.R19 ; IC13.R14 77.55,37.17 v2(77.95,36.76) 77.56,36.37 IC13.P14 ; IC13.AJ11 79.95,48.37 v2(80.35,48.77) ; v2(73.95,46.37) 73.95,47.17 IC13.AH19 ; IC13.AR35 v2(60.35,53.57) ; IC13.V10 v2(80.35,39.97) IC13.W11 ; IC13.Y17 75.16,41.17 v2(75.55,41.57) ; IC13.AT23 v2(70.75,54.37) ; IC13.M10 v2(80.35,35.16) ; IC13.AF35 v2(61.15,46.37) ; IC13.AE35 v2(61.15,45.57) ; v2(73.95,27.16) 73.95,27.17 73.95,27.17 IC13.C19 ; IC13.AB19 73.55,42.77 v2(73.95,43.17) ; v2(85.15,50.37) 85.55,49.97 IC13.AL4 ; v2(72.35,44.77) 71.95,44.37 IC13.AD21 ; IC13.AJ17 75.15,48.37 v2(75.55,48.77) 75.95,48.37 IC13.AJ16 ; v2(66.75,47.17) 66.35,47.57 IC13.AH28 ; IC13.AC17 v2(75.55,43.17) ; IC13.AB21 v2(72.35,42.37) ; IC13.L15 76.75,34.77 v2(76.35,35.16) 75.95,34.76 IC13.L16 ; v2(65.15,52.77) 65.15,52.77 IC13.AR29 ; IC13.AJ25 v2(68.35,48.77) ; v2(73.95,44.77) 73.55,44.37 IC13.AD19 ; IC13.AT20 v2(73.15,53.57) ; v2(74.75,44.77) 74.35,44.37 IC13.AD18 ; IC13.AE11 v2(79.55,45.57) ; IC13.AH11 79.96,47.57 v2(80.35,47.97) ; v2(86.75,35.96) 86.75,35.96 IC13.N3 ; IC13.AR34 v2(61.95,53.57) ; IC13.L22 v2(71.55,33.56) 71.55,33.56 IC13.K22 ; IC13.V28 66.35,39.57 v2(66.75,39.97) ; IC13.T23 v2(70.75,37.56) 70.36,37.17 IC13.R23
  TOP w0.406: v1(150.24,80.9) 150.24,80.34 C43.1 ; v1(151.76,80.9) 151.76,80.34 C43.1 ; R48.2 v1(82.53,22.77) ; v2(34.12,35.8) 34.52,36.2 U9.B9 ; C222.1 v1(10.03,67.07) ; C222.1 v1(11.41,68.49) ; C222.1 v1(12.95,67.07) ; R588.1 v1(93.99,69.4) ; R115.1 v1(89.89,90.59) ; v1(79.86,63.03) 79.83,63 R75.1 ; C377.2 v1(139.55,30.39) ; R56.1 v1(93.32,27.98) ; Y4.2 v1(138.14,45.26) ; C169.1 123.62,101.6 v1(123.62,102.15) ; C169.1 121.97,101.62 v1(121.97,102.15) ; C169.1 v1(122.81,102.15) ; C51.1 14.76,4.74 v1(14.2,4.74) ; C51.1 v1(14.2,5.5) ; C51.1 14.76,6.26 v1(14.2,6.26) ; IC9.5 v1(93.79,98.42) ; v1(143.87,22.9) 143.36,22.9 ANT2.4 ; C381.2 v1(23.85,74.05) ; R627.1 v1(38.89,51.69) ; C365.2 v1(129.64,37.63) ; U12.SH2 v1(5.7,29.77) ; v1(134.49,99.44) 134.49,100.35 C427.2 133.6,100.48 v1(133.6,99.44) ; T7.2 v1(10.7,59.73) ; U2.4 v1(89,75.92) ; C352.2 v1(33.5,22.73) ; C352.2 32.88,23.53 v1(33.5,23.53) ; C352.2 32.93,21.88 v1(33.5,21.88) ; R173.1 v1(79.1,58.97) ; C119.1 v1(155.52,90.81) ; U20.1 v1(76.56,10.32) TP20.1 ; v1(115.06,45.76) C342.2 ; C245.2 117.3,52.36 C330.2 v1(118.61,51.83) ; ANT1.4 109.96,21.37 v1(109.58,21.37) ; ANT1.4 v1(109.58,22.52) ; ANT1.4 110.08,23.53 v1(109.58,23.53) ; C340.2 v1(131.47,45.88) ; R176.2 v1(76.18,58.84) ; ANT4.2 v1(7.6,83.1) ; v2(57.78,25.96) 57.78,25.97 IC13.A38 ; C371.1 v1(132.94,39.41) ; v1(153.8,80.9) 153.8,80.34 C79.1 ; v1(28.57,90.46) 28.55,90.44 28.55,89.45 C114.2 v1(27.24,89.22) ; v1(84.3,100.37) 84.3,99.5 C84.2 85.07,99.46 v1(85.07,100.37) ; v1(49.12,81.7) 49.12,82.54 C107.1 ; R227.2 53.44,55.54 52.88,56.09 v1(52.88,56.09) ; v1(125.98,67.6) 126.34,67.96 C100.2 ; C353.2 129.03,69.79 v1(129.03,70.48) ; C353.2 130.56,69.84 v1(130.56,70.48) ; C353.2 v1(129.77,70.48) ; v1(161.25,43.07) C430.2 v1(162.66,41.69) ; C98.1 130.61,81.44 v1(130.61,80.73) ; C98.1 v1(131.29,80.73) ; C98.1 132,81.42 v1(132,80.73) ; L42.1 v1(128.02,32.17) ; R175.2 v1(71.96,90.23) ; ANT1.2 v1(114.73,23.99) ; v2(42.11,8.21) 42.51,8.61 U10.T9 ; C366.1 v1(131.11,27.37) ; TP7.1 v1(147.7,91.95) ; U12.6 v1(25.29,48.62) ; C0603.2 46.49,48.51 v1(47.2,47.81) ; C86.2 v1(152.91,66.42) ; R367.2 v1(34.01,84.75) ; v1(33.88,90.59) 33.88,91.68 C77.1 ; v1(30.07,68.87) 30.07,70.6 ; v2(72.35,36.76) 71.96,36.37 IC13.P21 ; v1(26.99,12.01) R567.2 28.26,11.89 ; v1(31.82,11.81) C346.2 v1(35.57,11.81) ; v1(92.29,42.38) 92.24,42.33 R40.2 ; v1(30.07,81.32) 29.57,80.81 R300.1 ; v1(142.85,9.44) 143.23,9.44 ANT3.4 ; R92.2 v1(94.97,92.88) ; ANT2.3 v1(138.84,25.39) ; ANT2.4 143.49,25.06 v1(143.87,25.06) ; ANT2.4 v1(143.87,23.91) ; U11.4 v1(93.73,53) ; 30.07,67.04 30.68,66.43 30.68,65.38 30.71,65.35 v1(30.71,65.32) ; 30.07,67.04 C297.2 29.44,66.51 v1(29.44,65.32) ; 30.07,67.04 v1(30.07,65.32) ; R642.1 v1(43.37,20.83) ; C127.1 v1(132.33,92.46) ; C422.2 v1(90,76.54) ; D20.1 v1(50.1,115.25) ; C351.2 v1(33.5,19.3) ; C351.2 32.88,20.1 v1(33.5,20.1) ; C351.2 32.93,18.45 v1(33.5,18.45) ; v1(77.83,108.62) C53.2 v1(76.75,107.42) ; C355.1 123.42,38.92 v1(122.73,38.92) ; C35.1 v1(74.78,106.72) ; C333.2 v1(129.52,51.57) ; v1(99.04,71.28) 99.01,71.31 L49.1 v1(97.93,70.14) ; R342.1 v1(134.34,50.08) ; T6.2 v1(98.97,14.71) ; L39.1 v1(128.02,33.44) ; C181.2 v1(71.96,98.49) ; R133.2 v1(68.05,106.84) ; C423.2 v1(90,74.38) ; v1(30.71,68.87) 30.71,69.96 C124.2 29.44,70.07 v1(29.44,68.87) ; C361.1 v1(131.06,33.41) ; v2(83.55,28.76) 83.95,29.16 IC13.E6 ; C77.1 v1(34.57,90.59) ; C77.1 35.28,91.66 v1(35.28,90.59) ; R366.2 v1(60.94,62.65) ; L31.1 v1(127.28,37.12) ; v1(151,80.9) C43.1 ; C426.2 v1(131.7,101.47) ; v2(59.28,46.9) 59.28,47.44 IC13.AH37 ; R253.2 v1(103.38,90.23) ; v1(146.81,69.85) 145.68,69.85 R109.2 v1(144.53,69.85) ; v1(96.2,93.47) C82.1 v1(97.29,92.33) ; R276.2 v1(109.58,17.69) ; R607.2 v1(129.92,101.73) ; IC13.AH38 58.35,47.55 58.62,47.28 v2(58.62,46.91) ; IC13.A8 82.88,25.44 v2(82.91,25.44) ; R354.1 v1(100.31,35.09) ; R76.1 v1(77.32,58.84) ; C325.1 v1(131.5,41.44) ; C171.1 v1(118.47,98.69) ; U19.2 v1(121.26,31.91) ; ANT2.2 v1(138.84,22.44) ; C250.2 v1(131.47,47.03) ; C79.1 v1(154.56,80.9) ; C79.1 155.32,80.34 v1(155.32,80.9) ; R172.1 v1(81.76,61.35) ; R258.1 v1(65.76,107.99) ; R256.1 v1(74.14,12.86) ; v1(39.62,20.07) 39.65,20.09 R643.1 ; L40.1 v1(128.63,36.23) ; C435.2 v1(143.23,34.96) ; C113.1 v1(17.14,81.53) ; R584.2 v1(94.64,84.39) ; R628.1 v1(39.88,56.25) ; U2.2 v1(87.3,73.64) ; R46.2 v1(85.99,57.15) ; v1(134.28,95.48) R85.1 v1(133.2,94.27) ; v1(89.89,88.43) 89.89,89.19 C341.2 90.61,89.15 v1(90.61,88.43) ; C107.1 47.73,82.66 v1(47.73,81.7) ; C107.1 v1(48.36,81.7) ; ANT4.3 v1(12.55,83.1) ; C389.2 v1(11.91,91.1) ; v1(80.37,59.54) C207.1 ; U10.P9 43.71,8.21 v2(43.71,8.21) ; C75.2 v1(64.01,104.99) ; T3.2 v1(107.15,13.86) ; C394.1 v1(67.92,110.15) ; R122.2 v1(146.81,91.69) ; IC13.AV38 v2(57.95,55.97) ; C239.2 v1(30.23,88.65) ; v1(50.72,56.09) 50.72,56.09 51.28,55.54 R228.2 ; IC13.AV1 v2(87.95,56.19) ; IC13.D7 83.15,28.36 v2(82.75,27.96) ; C439.2 v1(103.84,114.69) ; R458.2 v1(129.29,10.29) ; C144.2 v1(102.19,49.95) ; R77.1 v1(78.97,61.38) ; C102.2 v1(85.52,101.26) ; v1(80.75,63.03) 80.75,62.27 C202.1 ; C78.1 v1(95.25,99.58) ; D16.1 v1(85.21,102.67) ; R106.1 v1(100.31,37.38) ; ANT3.4 143.36,11.59 v1(142.85,11.59) ; ANT3.4 v1(142.85,10.58) ; C247.2 v1(50.19,112.7) ; C382.2 v1(27.03,74.05) ; U10.J2 v2(47.71,14.61) ; U12.3 v1(25.5,41.92) ; v1(131.7,54.71) 133.2,54.71 C210.2 132.63,54.01 v1(131.7,54.01) ; U24.1 v1(134.85,54.65) ; L26.1 v1(119.65,37.38) ; C386.2 v1(150.85,16.93) ; ANT4.4 v1(10.01,79.16) ; U12.SH1 v1(4.5,58.2) ; v1(153.5,30.03) C434.2 154.89,31.53 v1(154.92,31.56) ; U9.J2 v2(40.52,41.4) ; Y4.4 v1(134.21,42.96) ; C243.1 v1(15.37,86.61) ; R113.2 v1(17.02,83.69) ; R246.2 v1(75.92,106.72) ; R93.1 v1(100.31,36.23) ; ANT3.3 v1(147.88,9.1) ; v1(156.57,39.03) 156.31,39.28 C429.2 ; C319.1 v1(136.25,52.11) ; ANT3.2 v1(147.93,12.05) ; R362.2 v1(68.83,90.23) ; U10.M9 v2(45.31,9.01) ; C308.1 v1(149.2,5.18) ; C123.1 v1(26.8,116.59) ; R299.1 v1(30.2,79.54) ; C178.2 92.29,43.47 v1(92.3,43.47) ; U21.2 v1(129.13,30.39) ; C52.1 v1(24.77,4.51) ; C337.1 v1(119.23,27.47) ; C380.2 v1(20.93,26.94) ; C338.2 v1(83.54,19.47) ; v1(109.23,69.4) C416.2 ; v2(33.99,35.21) 34.33,35.21 U9.A9 ; C328.2 C331.2 v1(116.43,44.74) ; IC13.L3 v2(86.75,33.56) ; C248.2 v1(136.88,49.95) ; C388.2 v1(11.79,87.79) ; R102.1 v1(85.19,23.28) ; C134.2 v1(26.29,89.28) ; R53.1 v1(93.32,31.41) ; R297.2 v1(92.3,25.95) ; v1(127.13,100.2) 127.13,99.5 C163.1 128.02,99.38 v1(128.02,100.2) ; C109.1 v1(46.69,72.3) ; R250.2 v1(79.6,22.77) ; R117.1 v1(91.16,90.59) ; R229.2 v1(93.32,30.26) ; v1(133.77,34.84) C211.2 v1(133.77,36.93) ; R340.2 v1(128.5,37.25) ; R610.2 v1(157.71,45.76) ; C367.2 v1(131.47,44.61) ; L44.1 v1(118.96,34.76) ; R44.2 v1(81.38,22.77) ; R74.1 v1(77.32,61.38) ; C329.1 v1(131.5,42.71) ; R146.2 v1(49.66,111.38) ; R311.1 v1(20.95,76.58) ; C323.2 v1(117.96,20.74) ; C376.2 v1(139.55,27.09) ; R249.2 v1(78.46,22.71) ; C417.1 v1(108.52,68.83) ; U9.J8 v2(35.72,41.4) ; R171.1 v1(81.76,58.84) ; C354.2 v1(17.98,26.94) ; C224.2 v1(137.87,40.4) ; C242.2 v1(134.32,46.24) ; C405.2 C404.2 v1(93.99,84.37) ; C336.2 v1(136.88,46.9) ; C167.2 v1(129.54,99.35) ; T4.2 124.97,10.6 v1(125.45,11.09) ; C375.2 v1(121.26,20.74) ; ANT1.3 v1(114.61,21.04) ; T2.2 v1(100.67,91.73) ; R50.1 v1(93.32,29.12) ; C339.1 v1(135.36,59.22) ; C80.1 v1(154.31,70.99) ; R600.2 v1(89.42,78.93) ; C44.1 v1(153.03,70.99) ; v1(76.18,61.38) R177.2 ; C384.2 v1(132.06,80.02) ; C391.2 v1(76.18,4.48) ; R95.2 v1(94.97,91.61) ; C385.2 v1(150.85,13.63) ; C96.2 v1(81.64,97.45) ; C344.1 v1(123.17,27.47) ; C383.2 v1(129.16,80.02) ; C392.1 v1(72.62,110.15) ; R312.1 v1(17.02,80.9) ; C182.2 v1(68.83,98.49) ; R616.2 v1(96.62,120.18) ; C364.2 v1(130.18,51.4) ; C121.1 v1(133.6,92.46) ; C431.2 v1(153.14,50.46) ; R295.2 v1(88.11,22.77) ; R360.2 v1(72.49,106.84)
  TOP w0.508: IC12.4 v1(147.51,69.92)
  TOP w1.016: 122.62,25.54 135.57,25.54 135.57,29.28 ; 119.32,25.54 114.16,25.54 113.86,25.84 113.86,60.41 114.16,60.72 117.67,60.72 ; 153.39,42.33 153.26,42.2 ; 126.94,60.72 139.51,60.72 139.51,38.62 135.57,38.62 135.54,38.58 135.54,32.4
  BOTTOM w0.254: v1(157.96,24.29) 155.19,24.29 v1(154.92,24.57) ; v1(111.61,79.92) v1(113.23,79.92) v1(114.62,79.92) 116.42,79.92 v1(122.81,73.53) 128.55,67.79 v1(141.86,67.79) v1(147.83,67.79) 148.25,67.79 152.53,63.51 v1(152.53,63.5) 152.54,63.5 v1(157.96,58.08) ; v1(122.85,58.25) 122.84,58.25 122.79,58.2 v1(120.88,58.2) v1(117.09,58.2) v1(110.21,58.2) v1(107.39,58.2) 106.58,58.2 v1(105.79,57.42) 105.61,57.24 105.61,56.18 106.31,55.49 v1(108.61,55.49) v1(118.26,55.49) 118.34,55.41 120.5,55.41 120.88,55.79 v1(120.88,56.01) ; v1(87.99,63.03) v1(80.75,63.03) v1(79.86,63.03) v1(76.18,63.03) v1(74.65,63.03) v1(73.38,63.03) v1(72.16,63.03) v1(70.94,63.03) v1(69.72,63.03) v1(68.5,63.03) 65.25,63.03 64.75,63.54 v1(64.75,63.66) 64.75,64.86 65.17,65.28 v1(68.5,65.28) v1(72.16,65.28) v1(73.38,65.28) v1(74.65,65.28) v1(76.18,65.28) v1(85.95,65.28) 87.39,65.28 87.99,64.68 v1(87.99,63.03) ; v1(87.99,63.03) 94.82,63.03 v1(96.62,64.83) 99.04,67.25 v1(99.04,68.49) ; v1(112.12,77.13) 116.38,77.13 v1(124.46,69.05) 124.54,69.05 v1(125.98,67.6) 127.16,66.42 147.21,66.42 v1(150.91,62.71) 156.44,57.19 v1(156.44,55.03) 156.44,52.23 v1(156.57,52.11) v1(156.57,43.22) v1(156.57,39.03) v1(156.57,30.23) 156.57,27.01 157.12,26.45 v1(157.96,26.45) ; v1(64.23,61.33) 64.48,61.33 64.53,61.38 v1(68.5,61.38) v1(69.72,61.38) v1(70.94,61.38) v1(72.16,61.38) v1(73.38,61.38) v1(74.65,61.38) v1(76.18,61.38) v1(77.32,61.38) v1(78.97,61.38) 81.74,61.38 v1(81.76,61.35) ; v1(161.52,38.77) 161.52,41.19 159.74,42.96 v1(159.74,55.66) 159.74,56.3 v1(157.96,58.08) ; v1(157.96,58.08) v1(157.96,54.77) ; v1(154.92,26.33) v1(154.92,31.56) 154.94,31.58 v1(154.94,52.36) 154.94,56.53 v1(150.09,61.38) 146.57,64.9 126,64.9 116.05,74.84 110.72,74.84 v1(107.93,77.63) ; v1(122.91,59.54) 122.59,59.85 v1(118.24,59.85) v1(110.59,59.85)
  BOTTOM w0.305: IC2.36 101.95,32.67 v1(102.21,32.93) ; IC2.13 101.95,50.18 v1(102.19,49.95)
  BOTTOM w0.356: v1(101.32,86.14) 101.32,86.84 C95.1 100.69,86.84 v1(100.69,86.14) ; C150.2 61.87,52.68 v2(61.95,52.77) ; R36.2 59.69,54.23 v2(60.35,53.57) ; v2(34.12,45.4) 33.44,46.08 C443.2 ; v1(78.46,22.71) 78.46,21.87 C20.1 79.15,21.68 79.6,22.14 v1(79.6,22.77) ; U15.3 U15.8 v1(39.22,111.89) ; v2(35.72,41.4) 35.19,40.87 C446.2 ; v2(74.75,53.57) 74.32,54 C132.2 ; C155.2 v2(64.43,43.78) ; C130.2 70.04,47.08 v2(69.95,47.17) ; C437.2 v1(95.63,118.4) ; C241.2 121.26,38.03 v1(121.29,38.06) ; R618.1 v1(30.1,40.19) ; C496.2 v1(58.65,6.49) ; U16.8 U16.3 42.16,116.71 v1(42.67,117.22) ; U7.3 v1(152.68,33.84) ; v2(65.15,46.37) 64.81,46.37 64.35,45.91 C12.2
  BOTTOM w0.381: C61.1 67.38,44.94 v2(66.75,45.57) ; U23.5 112.66,43.71 R350.1 ; v2(69.15,45.57) 69.07,45.48 C10.2 ; C30.2 65.28,57.47 v2(64.49,56.68) ; C277.2 65.07,36.85 v2(65.15,36.76) ; C147.2 66.84,47.08 v2(66.75,47.17) 66.67,47.08 C156.2 ; C154.2 74.67,47.08 v2(74.75,47.17) ; v2(65.15,41.57) 65.07,41.48 C276.2 ; IC26.8 40.75,88.04 v1(40.36,88.43) 40.62,88.69 IC26.9 ; v2(62.74,36.36) C301.2 ; C285.2 65.07,39.88 v2(65.15,39.97) ; v2(75.55,47.17) 75.64,47.08 C219.2 ; v2(77.15,47.17) 77.24,47.08 C220.2 ; v2(61.21,36.83) 61.21,36.11 C283.2 ; v2(72.35,48.77) C233.2 ; v2(78.75,47.17) 78.84,47.08 C221.2 ; C305.2 v2(62.75,35.16) ; IC26.5 v1(48.51,89.34) ; 72.35,31.88 C279.2
  BOTTOM w0.406: v2(57.95,55.97) 58.16,56.17 C4.2 59.73,56.14 v2(58.75,55.17) ; v2(36.83,40.77) 37.49,40.77 C457.2 ; v2(61.15,40.77) 60.68,40.77 C312.2 ; C57.1 v2(83.55,44.77) ; C326.2 131.11,47.38 v1(131.47,47.03) ; C424.2 129.13,103.15 129.41,102.87 v1(129.41,102.74) ; v1(90.02,33.82) 90.15,33.69 R73.2 ; C45.1 v1(54.33,79.92) ; v2(85.95,54.37) 85.91,54.41 C234.2 v2(85.91,56.48) ; R12.1 C46.1 v1(54.33,78.4) ; C249.1 v1(118.47,37.5) ; v1(52.24,88.62) C94.1 v1(53.32,89.7) ; C16.2 v2(73.15,43.17) ; v2(68.54,56.63) 68.33,56.85 C59.2 C58.2 ; v1(43.43,42.75) C459.2 ; C13.2 v2(75.55,41.57) ; v2(69.15,27.97) 68.55,27.37 R197.2 68.63,27.18 ; v1(25.88,78.02) 25.88,77.18 C143.1 26.35,76.96 26.65,77.25 v1(26.65,78.02) ; v2(33.9,39.4) 33.6,39.4 33.22,39.78 C441.2 ; C475.2 C478.2 v1(50.06,17.28) ; v2(39.72,35.8) 39.65,35.73 C448.2 ; R194.2 78.4,27.28 78.75,27.63 v2(78.75,27.96) ; v2(65.15,34.36) 65.24,34.28 C294.2 ; C159.2 74.67,36.68 v2(74.75,36.76) ; v2(70.08,50.91) 70.75,50.91 C213.2 70.82,51.64 v2(70.08,51.64) ; C40.1 v2(73.94,31.04) ; v2(78.97,26.58) 78.78,26.39 C25.1 79.48,25.44 v2(79.86,25.06) ; v2(76.33,29.73) 76.36,29.74 C7.2 ; C81.1 v1(43.92,93.26) ; v2(70.75,27.16) 70.52,26.93 C24.2 ; v2(63.68,47.75) 62.93,47.75 C296.2 62.99,47.05 v2(63.68,47.05) ; v1(55.47,82.08) 54.52,82.08 C18.2 v1(54.27,80.68) ; v2(71.55,35.96) 71.55,35.87 71.16,35.47 71.13,35.47 C291.2 ; v1(92.29,42.38) 91.99,42.68 R42.2 ; IC14.4 v1(10.01,50.84) ; v1(23.85,29.88) C255.1 v1(22.43,31.28) ; v2(71.55,28.76) 71.27,29.04 C284.2 ; v1(4.36,61.89) R116.2 v1(3.28,60.87) ; C2.2 v2(75.55,39.17) ; C41.1 76.44,35.08 v2(76.35,35.16) ; v1(66.35,51) C227.2 v1(65.21,49.97) ; v2(61.15,27.16) 61.21,27.23 C280.2 ; C160.1 v1(31.24,94.61) ; v2(70.75,39.97) 71.55,39.97 C23.2 71.55,40.77 v2(70.75,40.77) ; v2(61.15,33.56) 61.49,33.9 C295.2 ; C21.2 v2(76.35,31.24) ; v1(90.02,32.51) 90.06,32.55 R72.2 ; C153.1 v1(15.49,94.61) ; v2(73.95,27.96) 73.91,28 C289.2 ; v2(82.68,29.97) 82.68,29.15 C19.2 81.98,29.46 v2(81.98,29.97) ; C315.2 v2(69.22,31.19) ; C313.2 60.96,49.78 v2(61.21,49.53) ; C483.2 47.24,7.14 47.24,7.12 47.6,6.77 47.64,6.77 v2(47.73,6.68) 47.8,6.68 48.33,7.2 C485.2 ; C201.1 82.68,40.77 v2(82.8,40.89) ; v1(119.74,51.14) C321.2 C317.2 ; C17.2 v2(77.15,43.17) ; v1(118.87,39.69) C362.2 C244.2 ; v1(31.85,42.07) 31.5,42.43 C466.2 C465.2 ; v2(72.35,52.77) 72.37,52.78 C235.2 ; v2(41.53,38.54) 41.5,38.51 C449.2 ; C29.2 v1(50.78,75.73) ; C491.2 44.22,7.7 v2(43.71,8.21) ; v1(49.82,74.08) 49.82,73.44 C27.2 50.52,73.38 v1(50.52,74.08) ; C217.2 v2(78.79,51.11) ; v1(14.81,55.5) C115.2 C112.1 ; v2(65.15,47.97) 65.07,48.05 C22.2 ; v1(38.35,32.84) 38.1,33.09 R623.1 ; U4.2 v1(161.52,38.77) ; v2(54.12,8.21) 54.12,8.95 C495.2 ; C306.2 v2(69.92,30.73) ; v2(54.12,15.41) 53.79,15.09 C487.2 ; R290.1 v1(21.84,46.99) ; C461.2 36.72,40.01 v2(36.52,39.8) ; v1(56.85,13.74) C477.2 C479.2 ; C488.2 50.85,13.88 v2(50.92,13.81) ; v1(95.52,78.29) 95.49,78.27 C411.2 ; C175.2 74.67,33.48 v2(74.75,33.56) ; v2(75.62,49.97) C214.2 v2(76.75,50.97) ; C480.2 52.37,15.41 v2(52.52,15.41) ; C418.2 v1(104.12,81.32) ; C133.2 v2(82.75,39.57) ; v2(59.55,31.96) 59.16,31.57 C290.2 ; C226.2 87.03,48.25 v2(86.75,47.97) ; C118.2 v1(35.66,7.87) ; R648.1 v1(37.47,24.42) ; v2(50.51,8) 50.11,8.4 C494.2 ; C363.2 v1(130.79,40.17) ; C469.2 v1(47.24,4.39) ; C287.2 62.36,27.56 61.95,27.96 v2(61.95,28.76) ; v1(127.04,51.02) 126.98,50.95 126.98,50.94 C360.2 ; C39.1 v2(80.34,31.96) ; C421.2 v1(101.64,80.17) ; R639.1 v1(52.62,4.36) ; v1(121.45,51.15) 122.02,50.58 C318.2 ; R155.2 91.02,39.75 R67.2 v1(89.47,40.96) C26.1 v1(89.47,43.09) ; v2(62.74,32) R195.2 ; C173.2 78.96,29.74 v2(78.99,29.73) ; R192.2 v2(69.15,39.17) ; C408.2 v1(101.58,76.54) ; C311.2 v2(69.11,28.85) ; v2(87.56,32.1) 88.24,32.1 88.68,32.55 C48.2 89,32.36 v2(89,31.54) ; C145.2 v2(83.55,47.17) ; C304.2 61.09,43.69 60.81,43.97 v2(60.35,43.97) ; C8.2 v2(75.55,43.17) ; v1(100.9,113.6) 100.9,114.57 C438.2 101.68,114.59 v1(101.68,113.58) ; C162.2 C158.2 72.03,27.64 v2(72.35,27.96) ; C281.2 v2(66.75,31.17) ; v2(62.08,42.2) 62.71,42.2 C31.1 62.76,43.02 v2(62.08,43.02) ; C176.2 v1(95.35,96.43) ; C415.2 v1(98.56,77.4) ; C246.2 123.67,51.73 v1(123.17,51.22) 123.29,51.1 C254.2 ; v2(84.35,53.57) 84.44,53.65 C139.2 ; v2(77.95,35.16) 78.67,34.45 C128.2 ; C433.2 v1(151.99,31.53) ; v1(75.95,56.26) 76.2,56.01 C212.1 ; v2(81.15,52.77) 81.36,52.56 C223.2 ; C474.2 53.62,17.28 v1(53.77,17.13) ; C343.2 128.16,50.43 128.4,50.67 128.4,50.72 v1(128.47,50.79) ; v1(100.44,74.89) 100.57,74.76 C409.2 ; C6.2 v2(69.95,40.77) ; C482.2 v2(47.98,11.96) ; C146.2 v1(21.23,41.3) ; C237.2 68.87,54.08 v2(68.35,53.57) ; v1(108.61,38.39) 108.94,38.72 C378.2 ; v1(20.45,89.15) 20.83,89.53 C151.1 ; R199.2 73.04,35.28 v2(73.15,35.16) ; C347.1 v1(36.51,4.74) ; v1(11.53,43.47) 10.4,43.47 C49.1 ; C272.2 81.64,25.06 v2(81.87,25.29) ; C410.2 v1(95.77,80.83) ; v2(36.83,41.4) 36.83,42.14 C442.2 ; v1(23.75,47.88) C148.2 v1(22.67,46.67) ; v1(97.99,78.23) C407.1 v1(96.88,79.31) ; C370.2 v1(125.58,39.3) ; v2(54.92,8.21) 55.35,7.77 C484.2 ; v1(84.45,45.59) 84.65,45.78 C197.2 84.65,47.56 v1(84.33,47.88) ; v2(47.71,14.61) 47.94,14.83 C490.2 ; C473.2 v1(39.55,17.94) ; v1(125.32,38.65) 124.84,38.65 C322.2 ; C282.2 v2(66.67,29.59) ; C292.2 v2(64.39,51.47) ; C205.1 78.54,56.01 v1(79.05,56.52) 79.24,56.32 C225.2 80.07,55.68 v2(79.55,55.17) ; v1(42.16,34.92) 42.24,34.85 C458.2 ; C67.1 v2(82.75,38.36) ; C208.2 v1(102.72,56.04) ; v1(90.3,82.23) C406.1 v1(91.52,81.09) ; R80.2 71.88,57.42 v1(72.16,57.7) ; v1(89.22,36.44) 89.22,37.21 C1.2 90.02,36.92 v1(90.02,36.44) ; v2(36.58,38.99) 36.7,38.86 C462.2 ; v2(88.75,46.01) 89.26,46.52 C72.2 ; C467.2 v1(30.35,48.39) ; C450.2 v1(30.71,50.96) ; C142.2 65.25,52.87 v2(65.15,52.77) ; v1(57.53,28.32) 58.01,27.84 C299.2 C275.2 ; C470.2 v1(46.1,4.39) ; C138.2 v2(65.31,51.29) ; C274.2 85.45,21.63 v1(85.19,21.88) ; v1(25.53,86.11) 25.65,86.23 C137.1 ; v1(31.62,38.61) C445.2 ; C91.1 v1(100.94,89.06) ; C374.2 126.59,41.59 v1(127.36,41.59) ; v2(33.99,35.21) 33.81,35.03 C452.2 ; v2(73.87,50.25) C216.2 ; v1(4.4,51.24) R121.2 v1(5.54,50.18) ; v2(84.05,32.8) R71.2 v2(82.97,31.72) ; v2(77.15,29.09) 77.11,29.05 C38.2 ; v2(41.53,37.54) 41.5,37.52 C447.2 ; C486.2 54.76,6.36 v1(54.81,6.41) ; C149.1 v1(26.29,78.87) ; T5.2 127.1,10.89 v1(127.38,11.18) ; v2(82.78,32.63) C63.2 v2(81.55,31.47) ; v1(31,42.07) 30.78,42.29 R624.1 ; v1(116.05,47.84) 114.8,47.84 C379.2 114.47,48.5 114.77,48.81 v1(115.8,48.81) ; v2(88.37,31.15) 89.26,30.26 C5.1 89.89,30.71 v1(89.89,31.86) ; C286.2 59.36,52.58 v2(59.55,52.77) ; C251.2 48.63,116.48 v1(48.62,116.5) ; C117.2 v1(7.47,59.73) ; v2(47.71,9.81) 48.09,9.44 C489.2 ; v2(39.72,44.6) 39.88,44.76 C455.2 C454.2 ; v1(99.83,76.64) 99.86,76.62 C412.1 ; C230.2 v1(81.15,51.17) ; R613.2 v1(143.23,32.8) ; v2(69.95,49.44) C236.2 ; C316.2 127.48,38.91 127.74,38.65 v1(127.74,38.63) ; C471.2 v1(48.39,4.39) ; U17.2 v1(23.62,94.87) ; C3.2 v2(69.95,38.36) ; v1(42.67,6.48) 42.89,6.26 R635.1 ; C300.2 59.33,46.15 v2(59.55,46.37) ; R17.2 61.84,39.05 v2(61.15,38.36) ; v2(87.56,44.77) 87.64,44.68 C122.2 ; C111.1 v1(15.22,42.79) ; C111.1 14.09,43.47 v1(15.22,43.47) ; C111.1 14.11,42.07 v1(15.22,42.07) ; C345.2 v1(119.05,49.44) ; v1(56.87,16.22) 56.77,16.32 R634.1 ; R190.2 61.23,31.25 v2(61.15,31.16) ; C186.1 v2(85.95,35.96) ; C198.1 v2(85.95,43.97) ; R169.1 v1(94.08,53.89) ; C15.2 v2(85.95,27.98) ; v2(83.8,38.01) 83.95,38.17 C199.2 v2(85.07,39.16) ; C232.2 82.96,52.56 v2(82.75,52.77) ; C50.1 v1(16,44.11) ; C310.2 v2(67.95,31.17) ; C131.2 62.74,52.78 v2(62.75,52.77) ; C348.2 32.73,3.76 v1(33.15,3.34) ; C9.2 v2(71.55,43.17) ; C303.2 59.71,43.17 v2(60.35,43.17) ; C231.2 v2(67.59,51.09) ; v2(34.12,47.8) 33.81,48.11 C444.2 ; v2(43.64,12.61) C476.2 ; C152.1 v1(25.5,90.3) ; v1(11.53,42.07) 10.43,42.07 C49.1 ; R145.1 v1(100.9,27.72) ; C493.2 v1(40.13,16.64) ; C302.2 v2(64.34,37.56) ; C229.2 v2(83.55,48.37) ; R350.1 v1(111.86,43.85) ; v2(82.75,27.96) 82.63,27.84 C106.2 ; D10.1 v1(45.75,114.2) ; T8.2 v1(109.45,93.87) ; C42.2 v2(70.75,41.57) ; C492.2 42.06,8.16 v2(42.11,8.21) ; v2(57.53,43.06) 57.76,43.06 R188.1 ; C368.2 v1(108.61,40.68) ; C180.1 v2(84.44,37.88) ; v1(95.52,76.13) 95.49,76.11 C420.2 ; v2(80.35,39.97) 79.95,39.56 C28.1 78.74,39.56 78.33,39.97 v2(77.15,39.97) ; C460.2 v1(33.76,50.96) ; v2(67.95,41.17) 68.44,40.68 C288.1 ; R329.2 v1(107.04,91.86) ; T9.2 v1(12.99,33.25) ; C49.1 v1(11.53,42.79) ; C309.1 v2(70.02,31.9) ; R79.2 73.15,57.47 v1(73.39,57.71) ; C56.1 v2(83.55,43.57) ; C497.2 v1(41.91,6.73) ; v1(13.46,89.66) 14.29,89.66 C136.1 14.29,88.9 v1(13.46,88.9) ; C200.1 v2(82.78,42.22) ; C456.2 v1(44.48,36.74) ; C279.2 v2(72.35,31.17) ; v2(70.75,54.37) 70.75,54.91 R226.1 69.95,55.54 v2(69.95,54.37) ; C14.2 v2(73.15,38.36) ; v1(31.62,36.32) C451.2 ; v1(116.71,113.6) 116.46,113.86 U3.2 ; D11.1 v1(48.77,114.2) ; C209.2 v1(102.97,28.49) ; C369.2 v1(132.72,47.05) ; 65.28,58.1 C30.2 ; C320.2 v1(121.28,38.92) ; C135.2 v2(83.55,45.97) ; C157.2 v2(78.67,31.88) ; R138.1 v1(103.99,52.74) ; C125.2 63.97,51.97 v2(64.36,52.36) ; v1(31.62,37.47) C453.2 ; v2(36.58,38.23) 36.74,38.23 36.74,38.21 C463.2 ; C215.2 v2(77.93,51.97) ; C177.2 v2(70.75,43.17) ; IC17.4 v1(26.13,9.82) ; C11.2 v2(71.55,38.36) ; C419.2 v1(95.49,79.46) ; C196.1 v2(82.75,37.16) ; C108.2 v1(51.28,92.37) ; C218.2 v1(132.72,51.98) ; C278.2 v2(63.28,31.02) ; U14.2 v1(46.86,110.74) ; v2(63.64,29.55) C298.2
  BOTTOM w0.508: R583.2 32.96,10.67 v1(32.49,10.2) ; v1(158.43,69.41) R104.2 v1(159.51,68.2) ; C174.2 v1(152.15,66.67)
  vias: v1(1.5,99.22) v1(1.5,94.14) v1(1.5,89.06) v1(1.5,83.98) v1(1.5,78.9) v1(1.5,73.82) v1(1.5,68.74) v1(1.5,63.66) v1(1.5,58.58) v1(1.5,53.5) v1(1.5,48.42) v1(1.5,43.34) v1(1.5,38.26) v1(1.5,33.18) v1(1.5,28.1) v1(1.5,23.02) v1(1.5,17.94) v1(1.5,12.86) v1(1.5,7.78) v1(1.75,123.1) v1(3.53,3.59) v1(3.91,71.16) v1(3.91,69.63) v1(4.04,72.68) v1(4.04,64.05) v1(4.17,95.03) v1(4.17,89.45) v1(4.17,88.43) v1(4.17,87.41) v1(4.17,85.64) v1(4.17,82.84) v1(4.17,80.05) v1(4.17,78.78) v1(4.17,77.51) v1(4.17,67.73) v1(4.17,66.46) v1(4.17,65.19) v1(4.29,96.68) v1(4.29,84.49) v1(4.29,74.84) v1(4.42,86.78) v1(4.55,81.57) v1(4.55,76.49) v1(4.67,92.62) v1(4.8,62.9) v1(4.93,126.02) v1(4.93,68.49) v1(4.93,66.97) v1(5.06,93.38) v1(5.06,89.45) v1(5.06,88.43) v1(5.06,73.32) v1(5.18,95.8) v1(5.18,94.4) v1(5.18,87.41) v1(5.18,85.89) v1(5.31,98.34) v1(5.31,83.86) v1(5.31,65.44) v1(5.44,78.9) v1(5.44,76.75) v1(5.56,64.55) v1(5.69,96.56) v1(5.69,95.03) v1(5.69,85) v1(5.69,74.46) v1(5.82,80.56) v1(5.82,75.6) v1(5.94,89.45) v1(5.94,88.43) v1(5.94,82.59) v1(5.94,63.03) v1(6.07,72.3) v1(6.07,66.59) v1(6.2,91.73) v1(6.2,90.46) v1(6.45,94.53) v1(6.45,93.26) v1(6.45,83.98) v1(6.45,77.25) v1(6.45,71.03) v1(6.45,69.63) v1(6.45,67.98) v1(6.58,95.8) v1(6.58,87.29) v1(6.58,81.44) v1(6.71,98.21) v1(6.71,86.27) v1(6.71,75.73) v1(6.83,96.68) v1(6.96,89.45) v1(6.96,88.43) v1(6.96,73.82) v1(7.09,91.73) v1(7.09,90.46) v1(7.09,84.75) v1(7.09,79.54) v1(7.09,78.4) v1(7.09,64.55) v1(7.09,1.31) v1(7.21,95.29) v1(7.34,98.46) v1(7.47,93.26) v1(7.6,87.29) v1(7.6,72.68) v1(7.6,70.27) v1(7.6,68.49) v1(7.72,66.59) v1(7.72,63.03) v1(7.85,126.78) v1(7.85,97.7) v1(7.98,91.73) v1(7.98,90.46) v1(7.98,65.44) v1(8.1,77.38) v1(8.23,94.02) v1(8.23,85.64) v1(8.23,70.65) v1(8.36,96.68) v1(8.61,75.6) v1(8.74,94.91) v1(8.87,74.08) v1(8.99,93.38) v1(8.99,91.73) v1(8.99,90.46) v1(9.12,78.27) v1(9.12,73.19) v1(9.12,71.79) v1(9.12,67.98) v1(9.25,89.7) v1(9.25,88.81) v1(9.25,87.92) v1(9.25,69.89) v1(9.37,97.45) v1(9.75,76.62) v1(10.01,93.26) v1(10.01,75.48) v1(10.01,71.67) v1(10.26,74.46) v1(10.26,69.89) v1(10.39,98.59) v1(10.39,97.07) v1(10.39,95.54) v1(10.39,68.36) v1(10.77,76.75) v1(10.77,73.95) v1(10.9,90.33) v1(10.9,89.45) v1(10.9,88.56) v1(11.02,72.55) v1(11.02,70.9) v1(11.15,96.05) v1(11.28,78.52) v1(11.41,94.65) v1(11.41,93.26) v1(11.66,89.95) v1(11.66,84.87) v1(11.66,75.09) v1(11.91,86.14) v1(11.91,72.68) v1(12.17,70.27) v1(12.17,1.31) v1(12.42,86.52) v1(12.42,77.76) v1(12.55,89.83) v1(12.55,71.41) v1(12.68,88.43) v1(12.93,126.78) v1(13.06,76.49) v1(13.18,87.16) v1(13.18,84.87) v1(13.18,81.95) v1(13.31,75.09) v1(13.31,71.54) v1(13.44,79.29) v1(13.82,83.73) v1(13.95,85.51) v1(13.95,81.95) v1(14.07,80.05) v1(14.45,76.36) v1(15.22,78.02) v1(17.25,1.31) v1(18.01,126.78) v1(22.33,1.31) v1(22.58,83.86) v1(22.58,81.83) v1(23.09,126.78) v1(23.6,82.84) v1(24.61,83.86) v1(24.61,81.83) v1(27.41,1.31) v1(27.81,8.38) v1(27.81,5.84) v1(28.17,126.78) v1(28.7,7.11) v1(29.59,8.38) v1(29.59,5.84) v1(32.49,1.31) v1(33.25,126.78) v1(37.57,1.31) v1(42.65,1.31) v1(43.41,126.78) v1(43.43,90.93) v1(43.43,89.03) v1(44.45,89.92) v1(45.34,90.93) v1(45.34,89.03) v1(47.73,1.31) v1(48.49,126.78) v1(52.81,1.31) v1(53.57,126.78) v1(57.89,1.31) v1(62.97,1.31) v1(63.73,126.78) v1(68.05,1.31) v1(68.81,126.78) v1(73.13,1.31) v1(73.89,126.78) v1(78.21,1.31) v1(78.97,126.78) v1(81.76,4.1) v1(84.05,126.78) v1(84.56,6.39) v1(89.13,126.78) v1(89.64,6.39) v1(94.21,126.78) v1(94.72,6.39) v1(99.29,126.78) v1(99.8,6.39) v1(104.37,126.78) v1(104.88,6.39) v1(105.59,23.62) v1(105.89,21.75) v1(106.15,26.07) v1(106.15,24.93) v1(106.27,22.9) v1(106.81,21.46) v1(106.78,20.36) v1(106.93,19.3) v1(107.06,24.13) v1(107.54,27.34) v1(107.54,23.41) v1(107.8,25.56) v1(107.8,21.25) v1(107.93,22.14) v1(108.43,19.6) v1(108.58,24) v1(109.2,28.49) v1(109.2,26.96) v1(109.32,25.31) v1(109.45,126.78) v1(109.86,19.81) v1(109.96,6.39) v1(110.47,26.33) v1(110.85,28.74) v1(110.87,30.23) v1(111.12,19.3) v1(111.23,27.47) v1(111.35,25.69) v1(111.74,14.64) v1(112.14,30.99) v1(112.14,29.72) v1(112.12,17.69) v1(112.12,16.04) v1(112.24,41.06) v1(112.24,13.75) v1(112.27,18.92) v1(112.37,27.47) v1(112.62,25.95) v1(112.75,28.49) v1(112.97,41.06) v1(113.13,15.79) v1(113.13,14.77) v1(113.39,18.33) v1(113.51,16.8) v1(114.02,19.21) v1(114.28,14.77) v1(114.3,13.84) v1(114.4,15.79) v1(114.53,126.78) v1(115.04,17.82) v1(115.04,6.39) v1(115.06,31.5) v1(115.32,37.85) v1(115.32,36.45) v1(115.32,35.31) v1(115.32,32.77) v1(115.42,30.01) v1(115.42,28.87) v1(115.55,27.98) v1(115.55,26.83) v1(115.67,16.67) v1(115.8,13.75) v1(115.95,23.62) v1(116.2,21.34) v1(116.18,15.28) v1(116.43,19.21) v1(116.43,17.94) v1(116.56,29.88) v1(116.56,28.74) v1(116.69,27.85) v1(116.69,26.71) v1(117.09,21.72) v1(117.07,19.85) v1(117.07,14.52) v1(117.22,23.24) v1(117.7,17.06) v1(117.96,18.07) v1(118.09,15.91) v1(118.21,36.61) v1(118.21,35.6) v1(118.21,34.58) v1(118.21,33.44) v1(118.21,32.3) v1(118.24,23.24) v1(118.59,15.15) v1(118.72,13.88) v1(119.1,19.85) v1(119.1,18.58) v1(119.25,21.72) v1(119.36,36.49) v1(119.36,35.47) v1(119.36,33.31) v1(119.36,32.17) v1(119.51,23.24) v1(119.61,126.78) v1(119.86,14.9) v1(120.12,18.45) v1(120.12,6.39) v1(120.4,21.72) v1(120.52,23.24) v1(120.63,19.72) v1(120.65,13.72) v1(120.78,28.19) v1(120.78,27.18) v1(120.78,26.29) v1(120.78,25.27) v1(120.78,24.13) v1(121.01,15.15) v1(121.28,45.34) v1(121.26,37.25) v1(121.26,36.23) v1(121.26,35.22) v1(121.26,34.07) v1(121.26,32.93) v1(121.26,18.33) v1(121.64,17.18) v1(121.64,16.17) v1(121.79,28.32) v1(121.79,27.3) v1(121.79,26.42) v1(121.79,24.26) v1(121.77,14.52) v1(122.4,13.88) v1(122.68,21.72) v1(122.78,20.1) v1(122.91,37.88) v1(122.91,36.87) v1(122.91,35.85) v1(122.91,34.71) v1(122.91,33.57) v1(122.91,32.42) v1(122.91,17.94) v1(122.91,16.29) v1(123.04,22.77) v1(123.04,15.02) v1(123.55,18.96) v1(123.57,43.31) v1(123.67,57.7) v1(123.67,56.68) v1(123.67,55.41) v1(123.7,47.37) v1(123.67,13.88) v1(123.8,16.17) v1(123.93,37.12) v1(123.93,36.11) v1(123.93,35.09) v1(123.93,33.95) v1(123.93,32.8) v1(123.93,31.66) v1(124.21,60.45) v1(124.18,29.63) v1(124.18,17.94) v1(124.44,21.37) v1(124.69,126.78) v1(124.82,27.85) v1(124.82,26.83) v1(124.94,23.91) v1(125.07,37.12) v1(125.07,36.11) v1(125.07,35.09) v1(125.07,33.95) v1(125.07,32.8) v1(125.07,31.66) v1(125.2,19.98) v1(125.2,18.96) v1(125.2,6.39) v1(125.32,30.26) v1(125.32,16.17) v1(125.45,29.25) v1(125.45,22.64) v1(125.45,17.94) v1(125.58,56.17) v1(125.96,58.2) v1(125.98,45.47) v1(125.96,27.85) v1(125.96,26.71) v1(126.21,17.18) v1(126.47,21.37) v1(126.47,17.94) v1(126.85,28.87) v1(127.23,23.79) v1(127.36,14.9) v1(127.48,56.3) v1(127.48,19.85) v1(127.61,59.22) v1(127.61,27.85) v1(127.61,26.83) v1(127.61,16.04) v1(127.74,22.52) v1(127.89,92.33) v1(127.89,90.3) v1(127.86,57.57) v1(127.99,18.33) v1(128.37,30.26) v1(128.37,29.25) v1(128.75,55.66) v1(128.75,27.85) v1(128.75,26.71) v1(128.91,91.31) v1(128.88,24.04) v1(128.88,21.25) v1(129.01,33.44) v1(129.01,16.42) v1(129.26,6.39) v1(129.39,19.85) v1(129.64,57.06) v1(129.64,54.27) v1(129.77,126.78) v1(129.79,92.33) v1(129.79,90.3) v1(129.77,27.85) v1(129.77,26.71) v1(129.77,17.82) v1(129.77,14.77) v1(129.9,58.84) v1(129.9,28.87) v1(129.9,22.64) v1(130.28,34.33) v1(130.91,54.77) v1(130.91,26.58) v1(131.17,21.12) v1(131.29,23.91) v1(131.42,57.57) v1(131.42,16.29) v1(131.67,59.09) v1(131.8,19.72) v1(132.06,14.64) v1(132.18,17.69) v1(132.31,22.52) v1(132.94,20.99) v1(133.07,28.23) v1(133.07,27.09) v1(133.33,33.44) v1(133.59,46.27) v1(133.58,23.79) v1(133.71,16.17) v1(133.83,44.11) v1(133.83,31.79) v1(133.83,14.52) v1(133.96,59.6) v1(134.09,19.6) v1(134.21,28.1) v1(134.21,26.96) v1(134.47,23.79) v1(134.47,17.56) v1(134.6,22.39) v1(134.85,126.78) v1(134.85,14.52) v1(135.36,20.87) v1(135.36,16.67) v1(135.87,19.34) v1(135.99,14.52) v1(136.5,58.97) v1(136.5,32.8) v1(136.63,6.51) v1(136.75,16.17) v1(136.88,17.44) v1(137.01,35.98) v1(137.01,34.58) v1(137.14,14.52) v1(137.26,33.69) v1(137.26,31.79) v1(137.64,59.09) v1(137.64,36.87) v1(137.64,20.74) v1(138.02,46.52) v1(138.15,47.92) v1(138.15,14.52) v1(138.28,35.85) v1(138.28,32.8) v1(138.28,19.21) v1(138.41,56.17) v1(138.41,49.19) v1(138.41,43.98) v1(138.41,42.46) v1(138.53,57.82) v1(138.66,15.91) v1(138.79,17.82) v1(138.91,34.07) v1(139.17,14.52) v1(139.29,31.66) v1(139.42,37.25) v1(139.55,18.71) v1(139.68,35.72) v1(139.68,33.95) v1(139.8,32.93) v1(139.93,126.78) v1(140.18,20.74) v1(140.18,14.52) v1(140.56,19.09) v1(140.95,5.5) v1(141.07,13.88) v1(141.33,15.15) v1(141.83,17.44) v1(141.83,16.29) v1(142.09,13.88) v1(142.34,15.15) v1(142.6,20.61) v1(142.85,17.44) v1(142.85,16.29) v1(143.23,19.34) v1(143.23,13.88) v1(143.49,15.15) v1(143.61,2.96) v1(143.99,17.44) v1(143.99,16.29) v1(144.37,13.88) v1(144.63,15.15) v1(144.88,20.48) v1(145.01,126.78) v1(145.14,17.44) v1(145.14,16.29) v1(145.39,13.88) v1(145.64,19.21) v1(145.64,15.15) v1(146.15,17.44) v1(146.15,16.29) v1(146.41,13.88) v1(146.66,15.15) v1(147.17,17.44) v1(147.17,16.29) v1(147.42,13.88) v1(147.68,15.15) v1(147.93,19.09) v1(148.18,17.44) v1(148.18,16.29) v1(149.71,12.74) v1(149.71,11.85) v1(149.96,15.79) v1(149.96,14.77) v1(150.09,126.78) v1(150.09,121.96) v1(150.09,116.88) v1(150.09,111.8) v1(150.09,106.72) v1(150.98,15.28) v1(150.98,10.07) v1(151.23,11.47) v1(151.87,12.1) v1(152.12,16.29) v1(152.12,13.63) v1(152.12,10.07) v1(152.5,14.9) v1(152.5,11.34) v1(152.63,1.69) v1(152.76,105.57) v1(157.71,1.69) v1(158.34,105.57) v1(162.79,1.69) v1(163.3,105.57) v1(166.98,4.99) v1(167.49,101.64) v1(167.62,98.21) v1(167.62,93.13) v1(167.62,88.05) v1(167.62,82.97) v1(167.62,77.89) v1(167.62,72.81) v1(167.62,67.73) v1(167.62,62.65) v1(167.62,57.57) v1(167.62,52.49) v1(167.62,47.41) v1(167.62,42.33) v1(167.62,37.25) v1(167.62,32.17) v1(167.62,27.09) v1(167.62,22.01) v1(167.62,16.93) v1(167.62,11.85) v1(167.62,6.77) v3(121.28,47.5) v3(121.28,43.31) v3(123.7,45.21) v3(125.98,47.5) v3(125.98,43.31) v4(6.35,17.91) v4(145.77,54.14)
